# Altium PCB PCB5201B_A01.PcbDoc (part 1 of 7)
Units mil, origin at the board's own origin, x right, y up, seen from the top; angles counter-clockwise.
Board outline 4527.56 x 2362.2 mil, 6 copper layers (Top Layer, GND Layer 2, Signal Layer 3, Signal Layer 4, VCC Layer 5, Bottom Layer), stack 61.221 mil thick; 361 components, 250 nets, 1223 pads, 1068 vias.
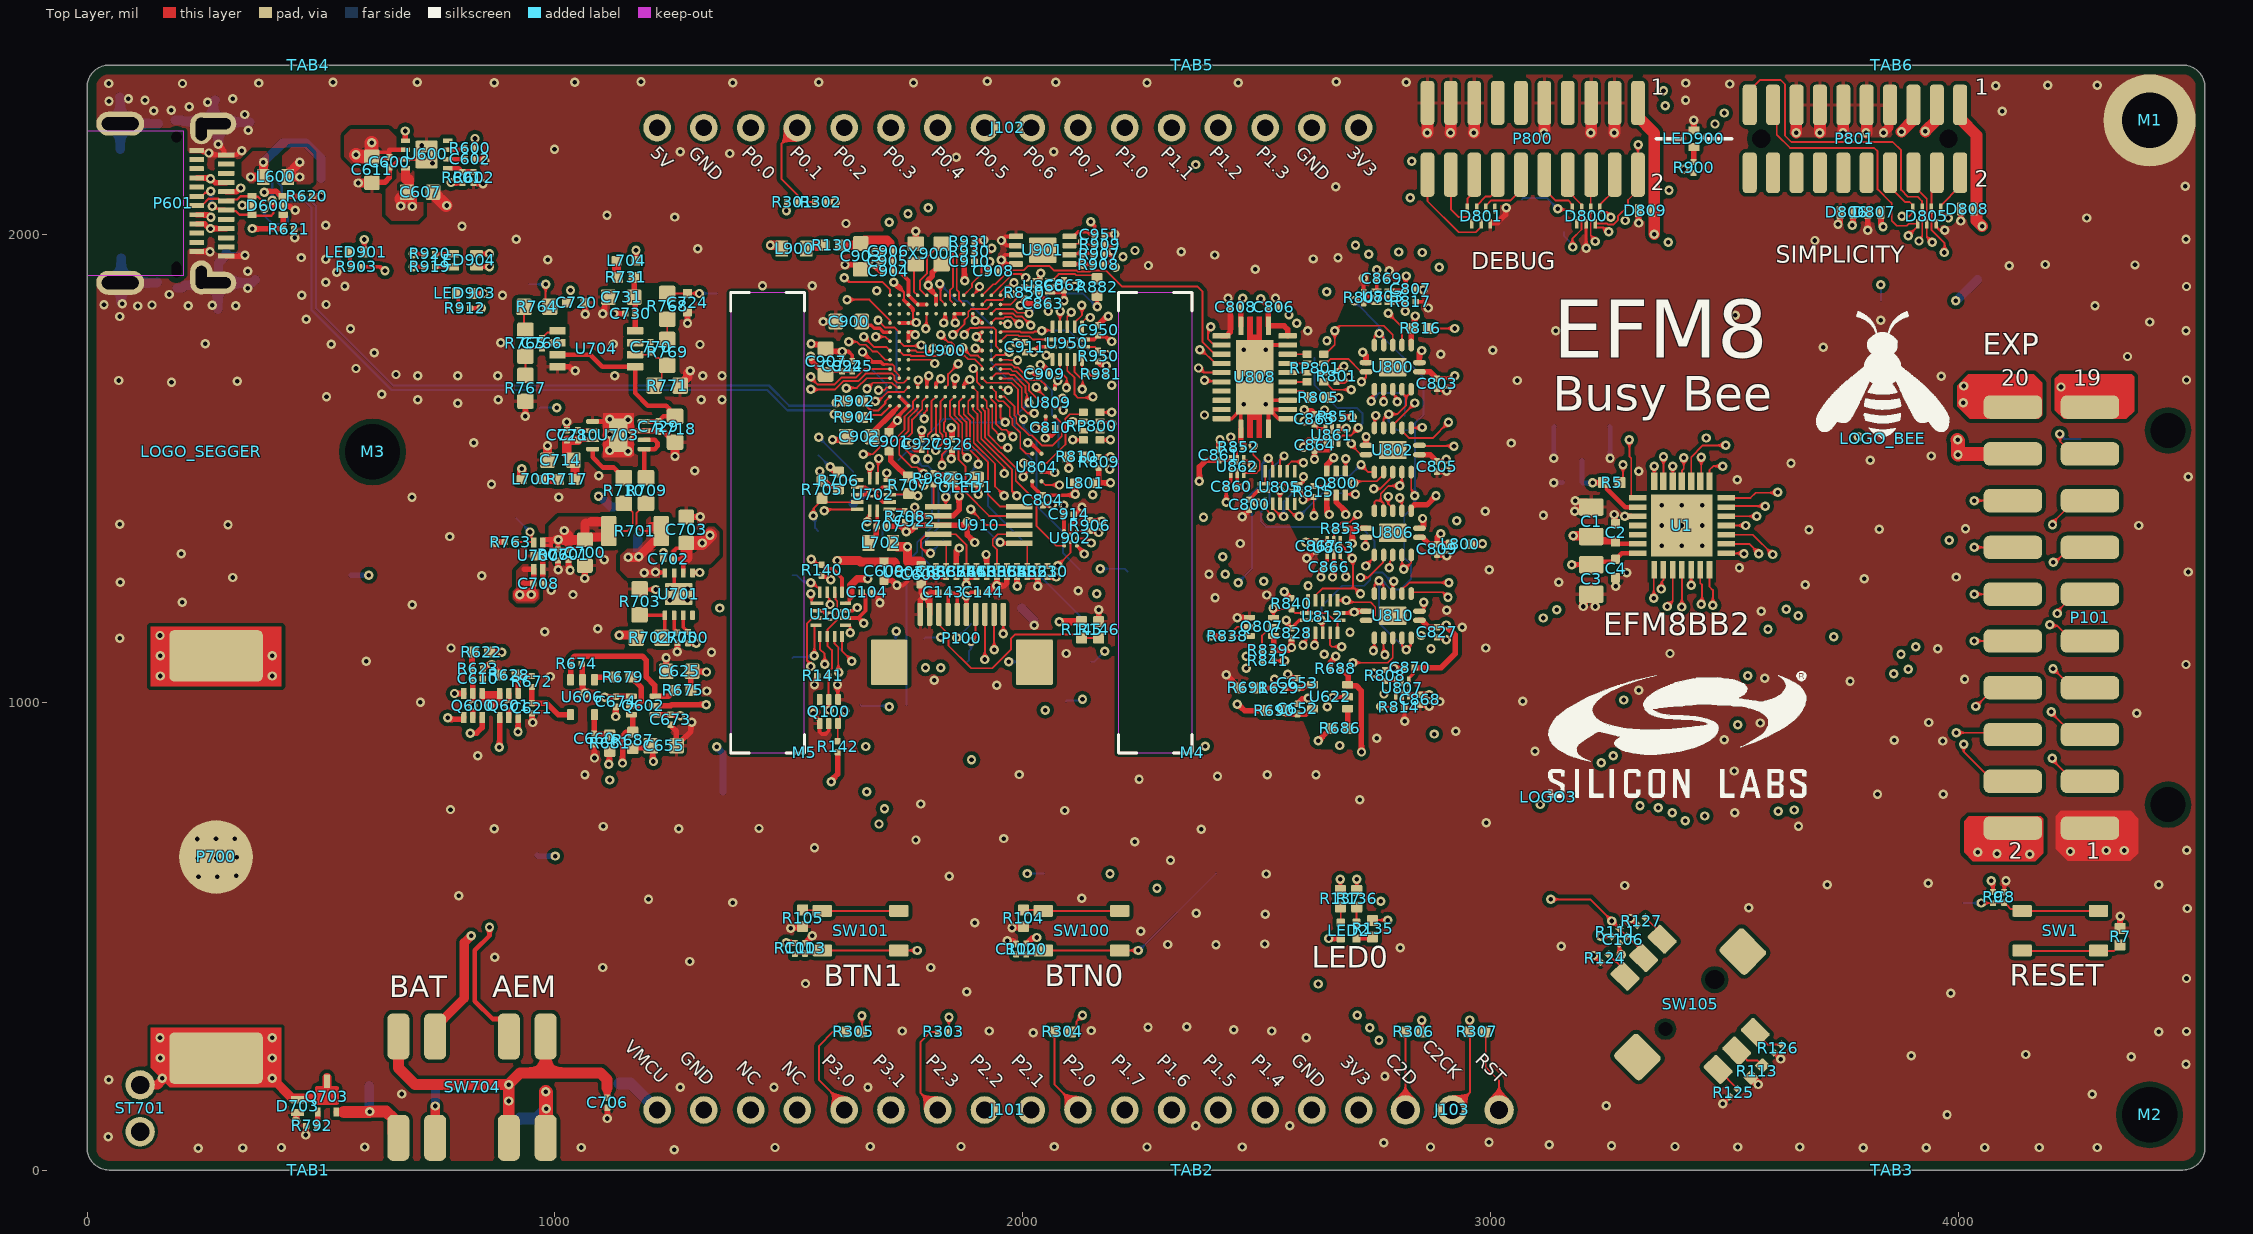
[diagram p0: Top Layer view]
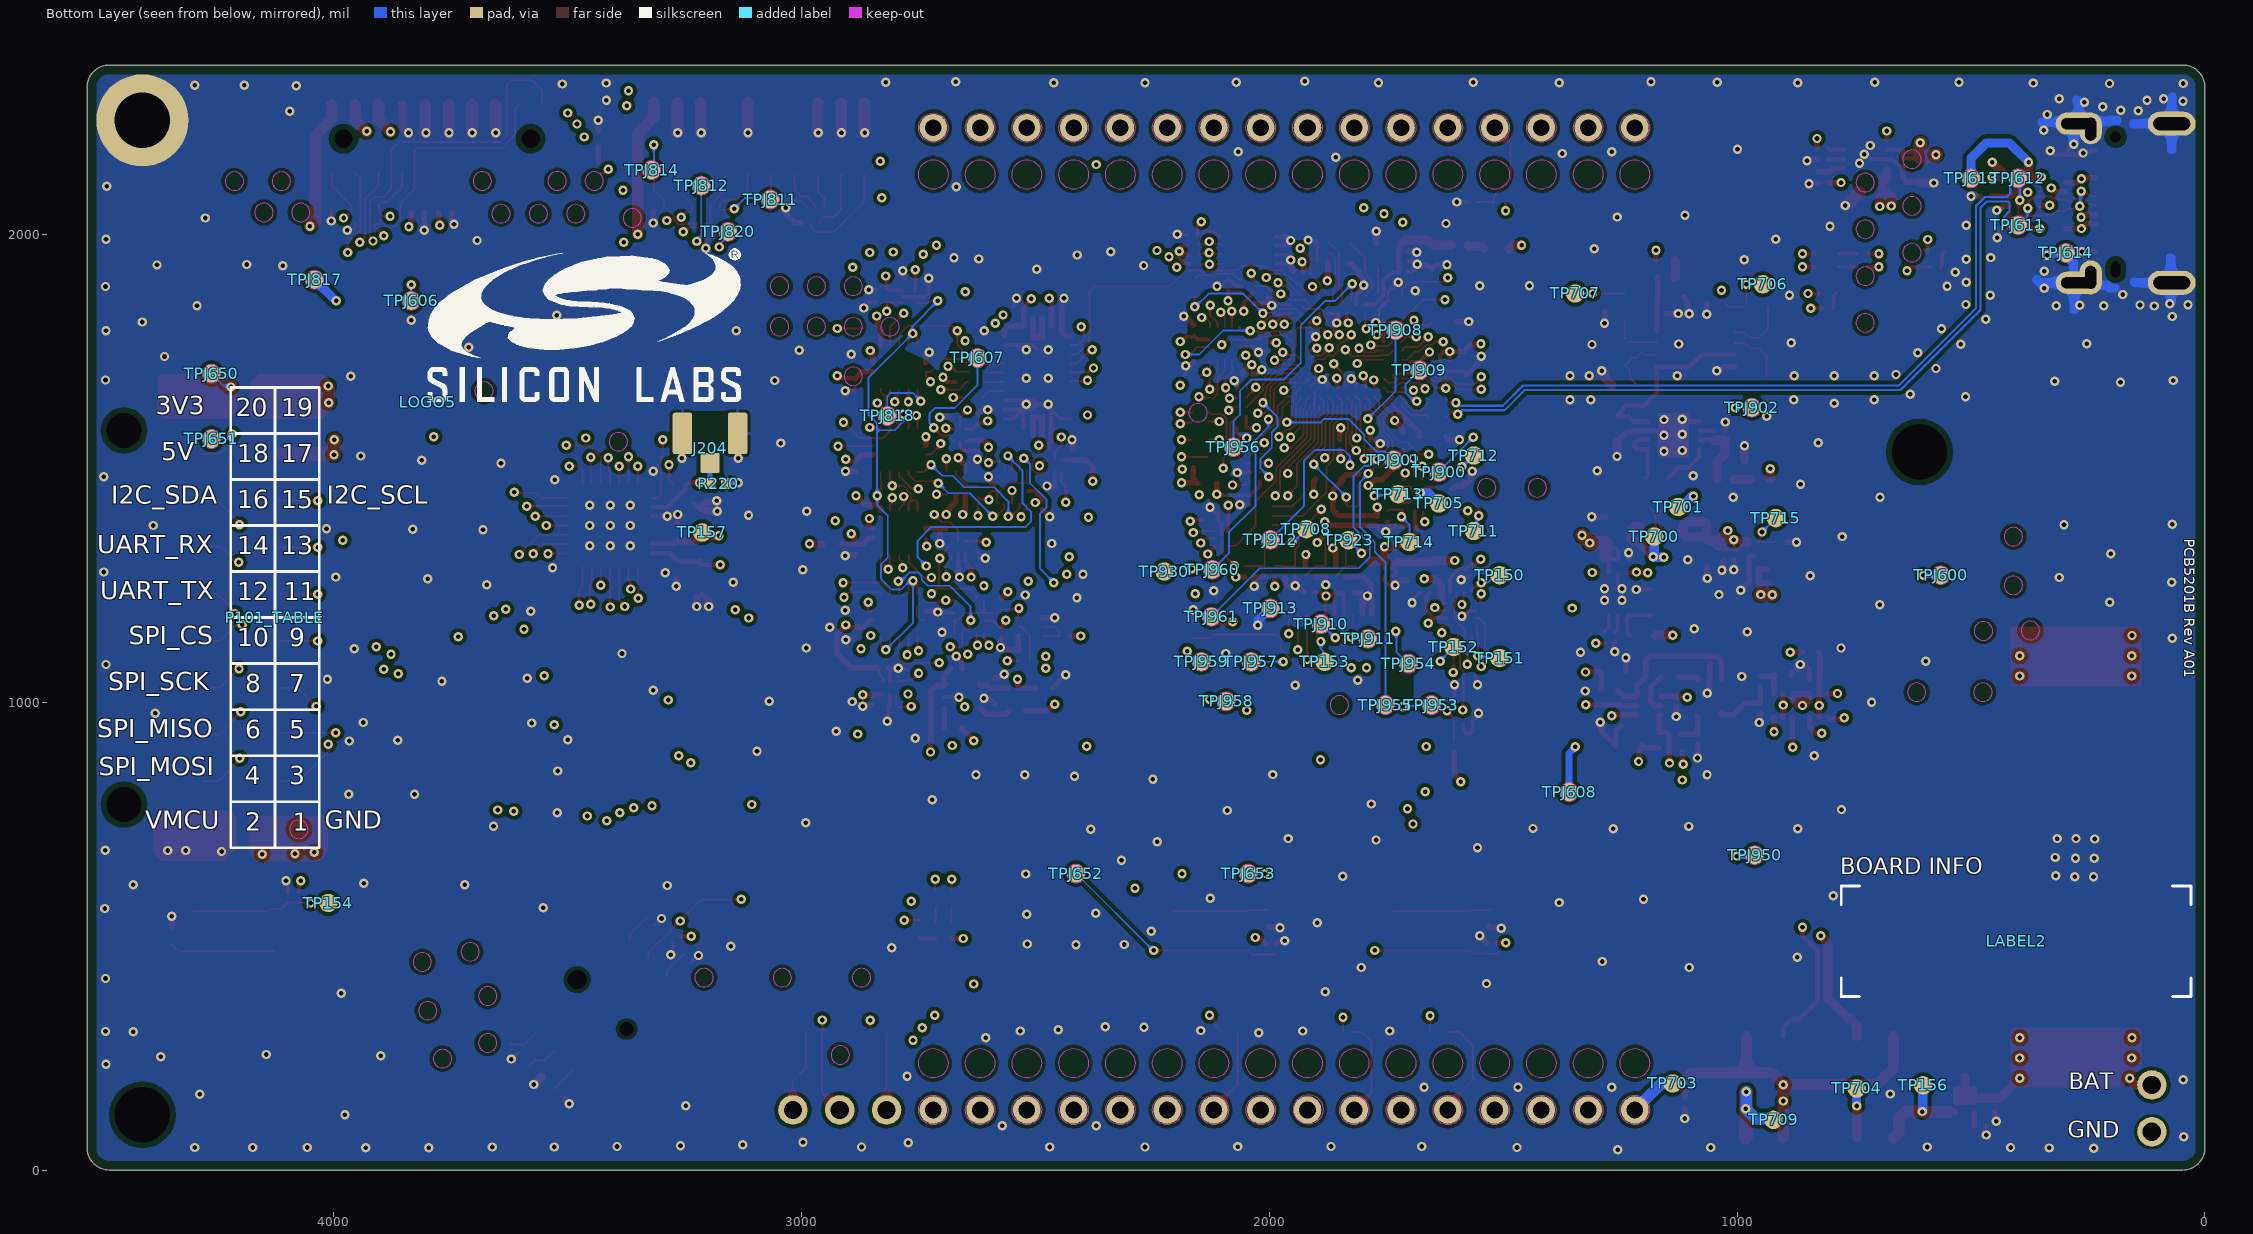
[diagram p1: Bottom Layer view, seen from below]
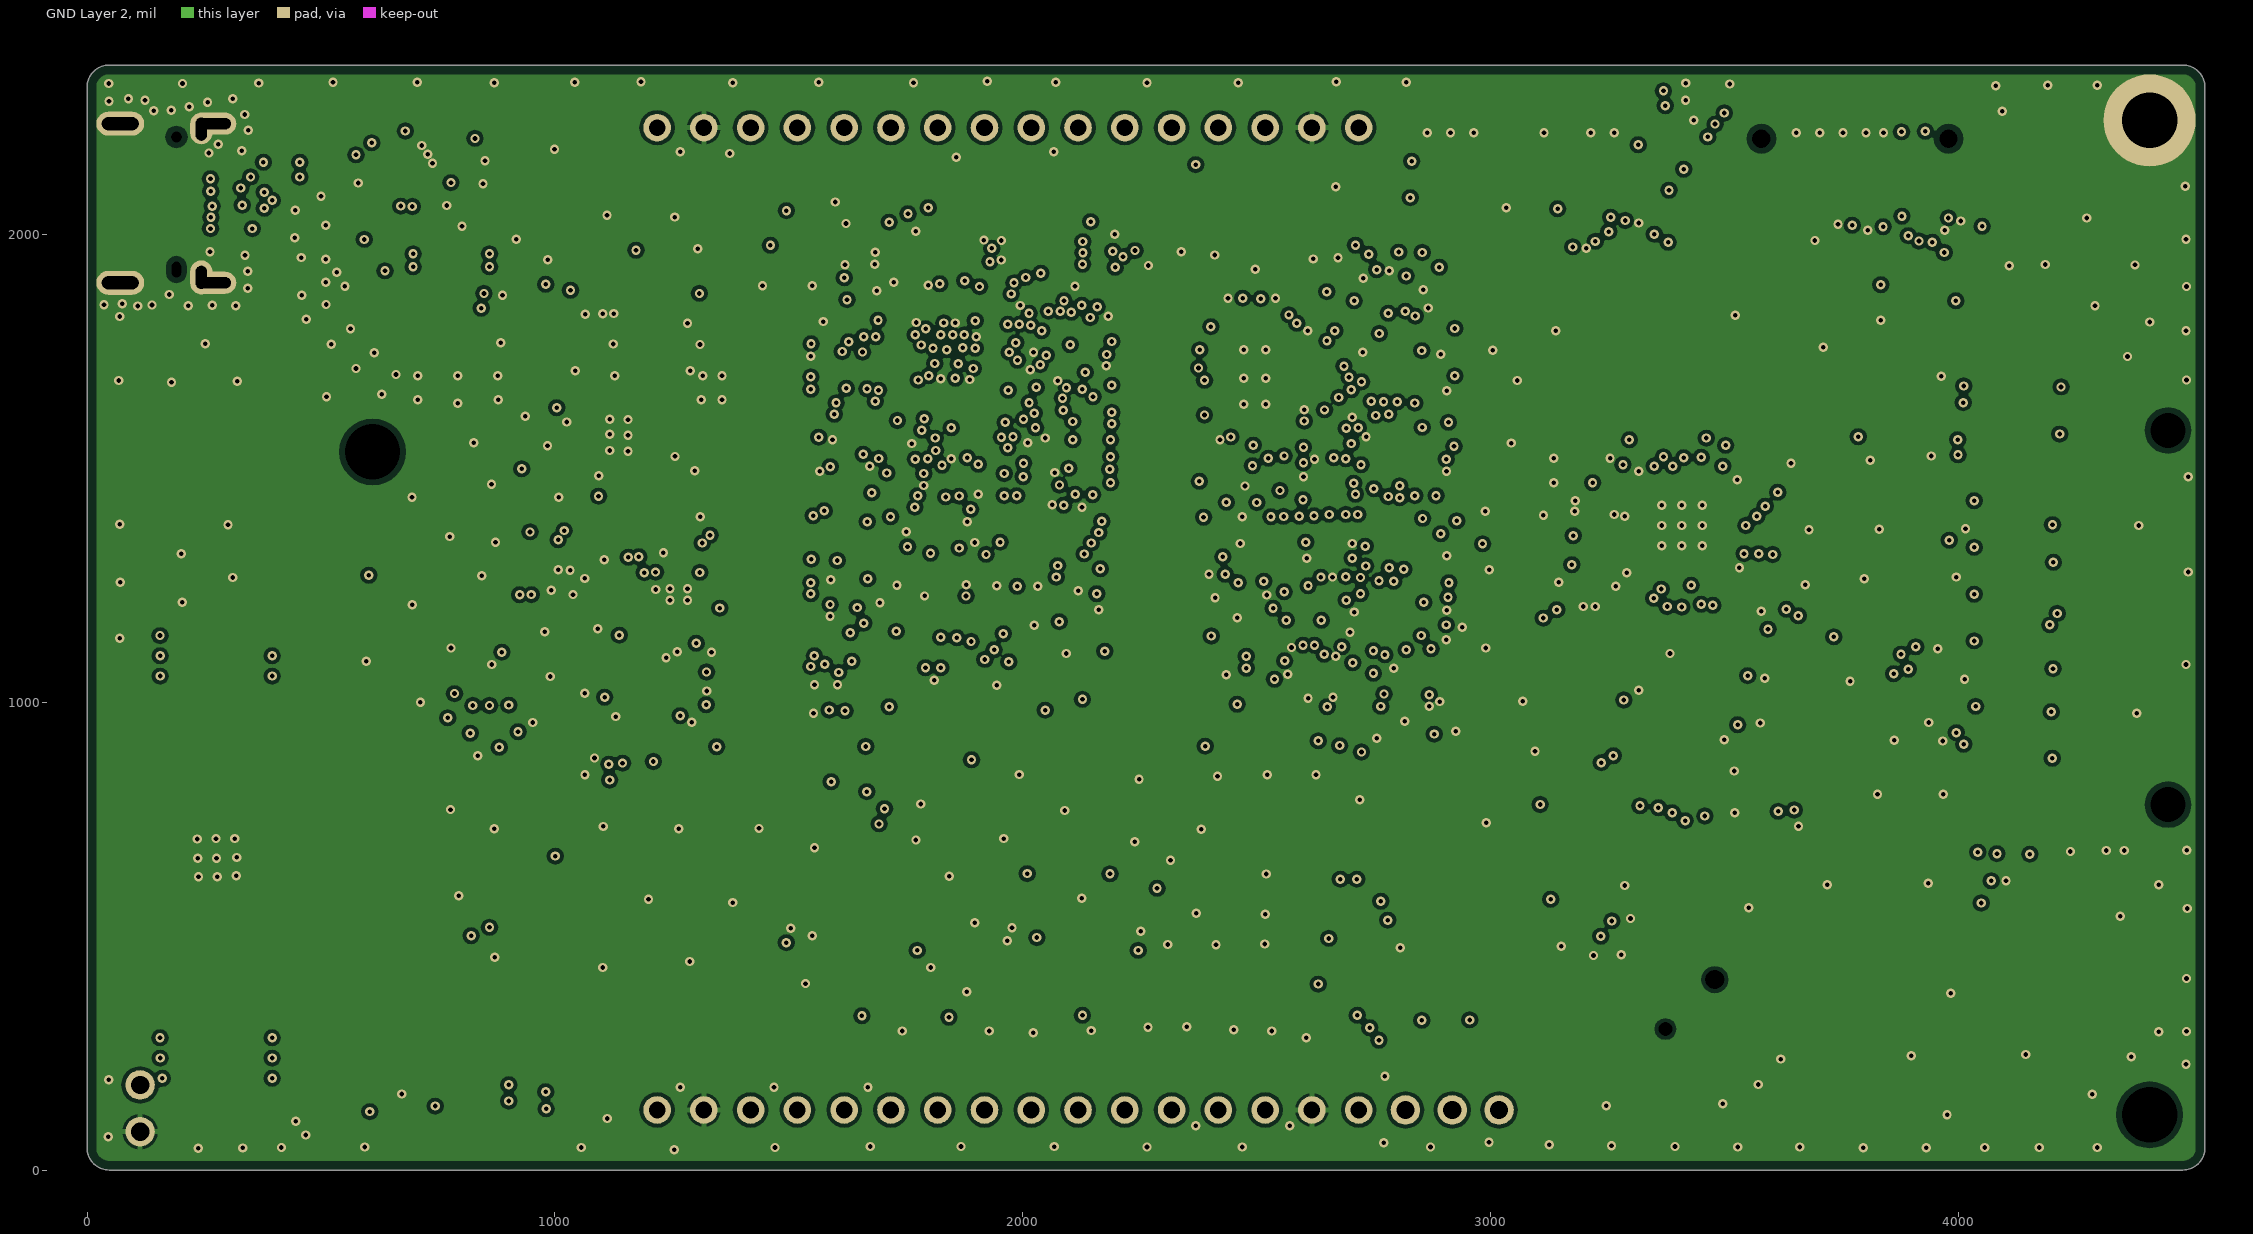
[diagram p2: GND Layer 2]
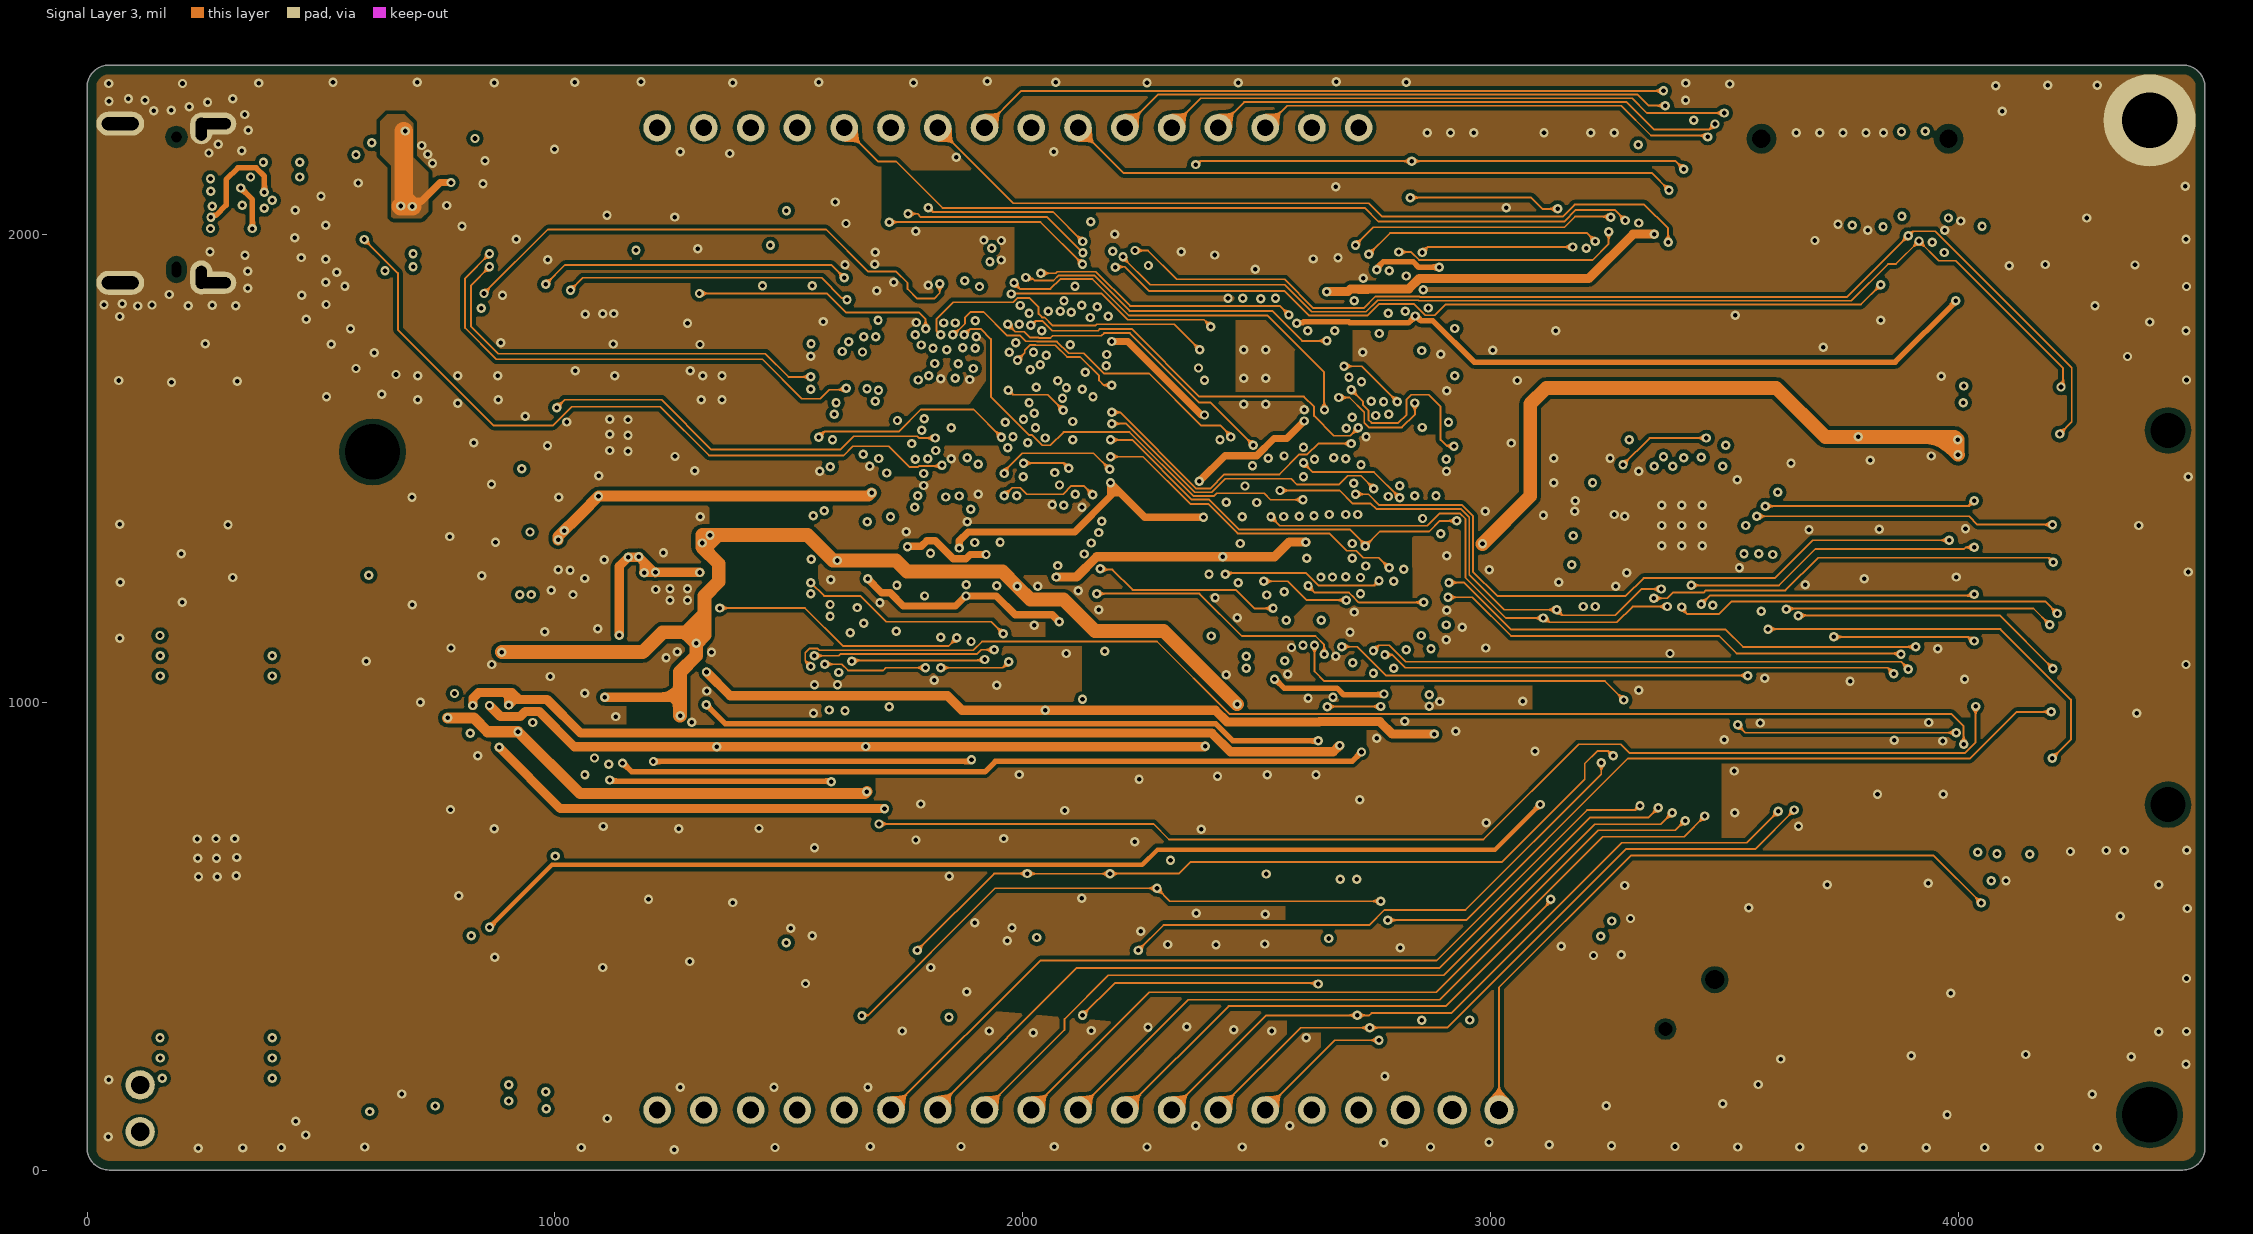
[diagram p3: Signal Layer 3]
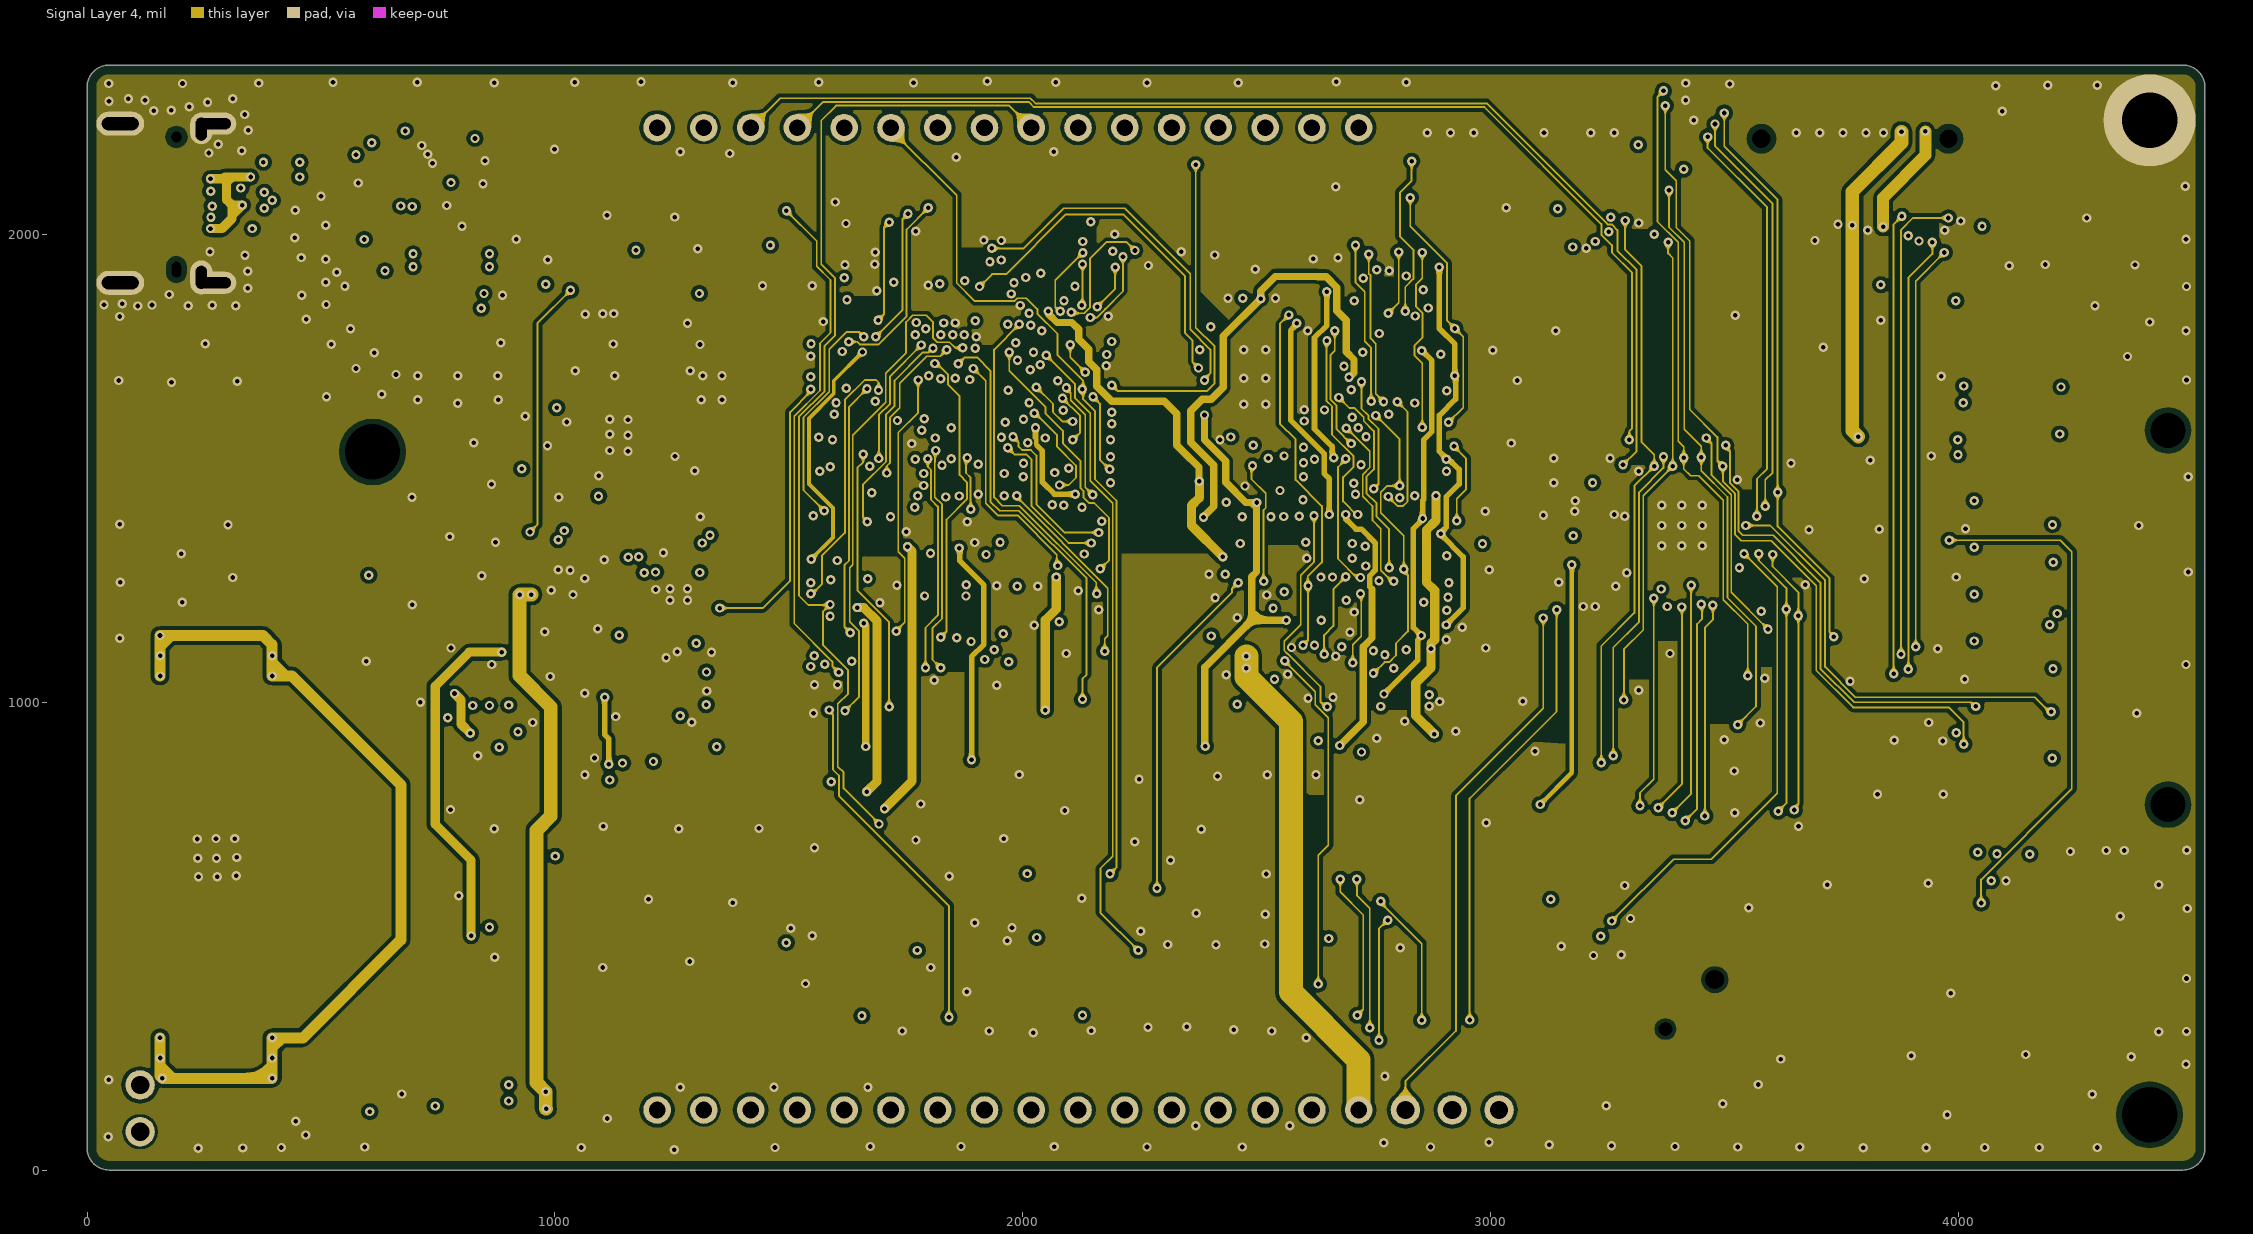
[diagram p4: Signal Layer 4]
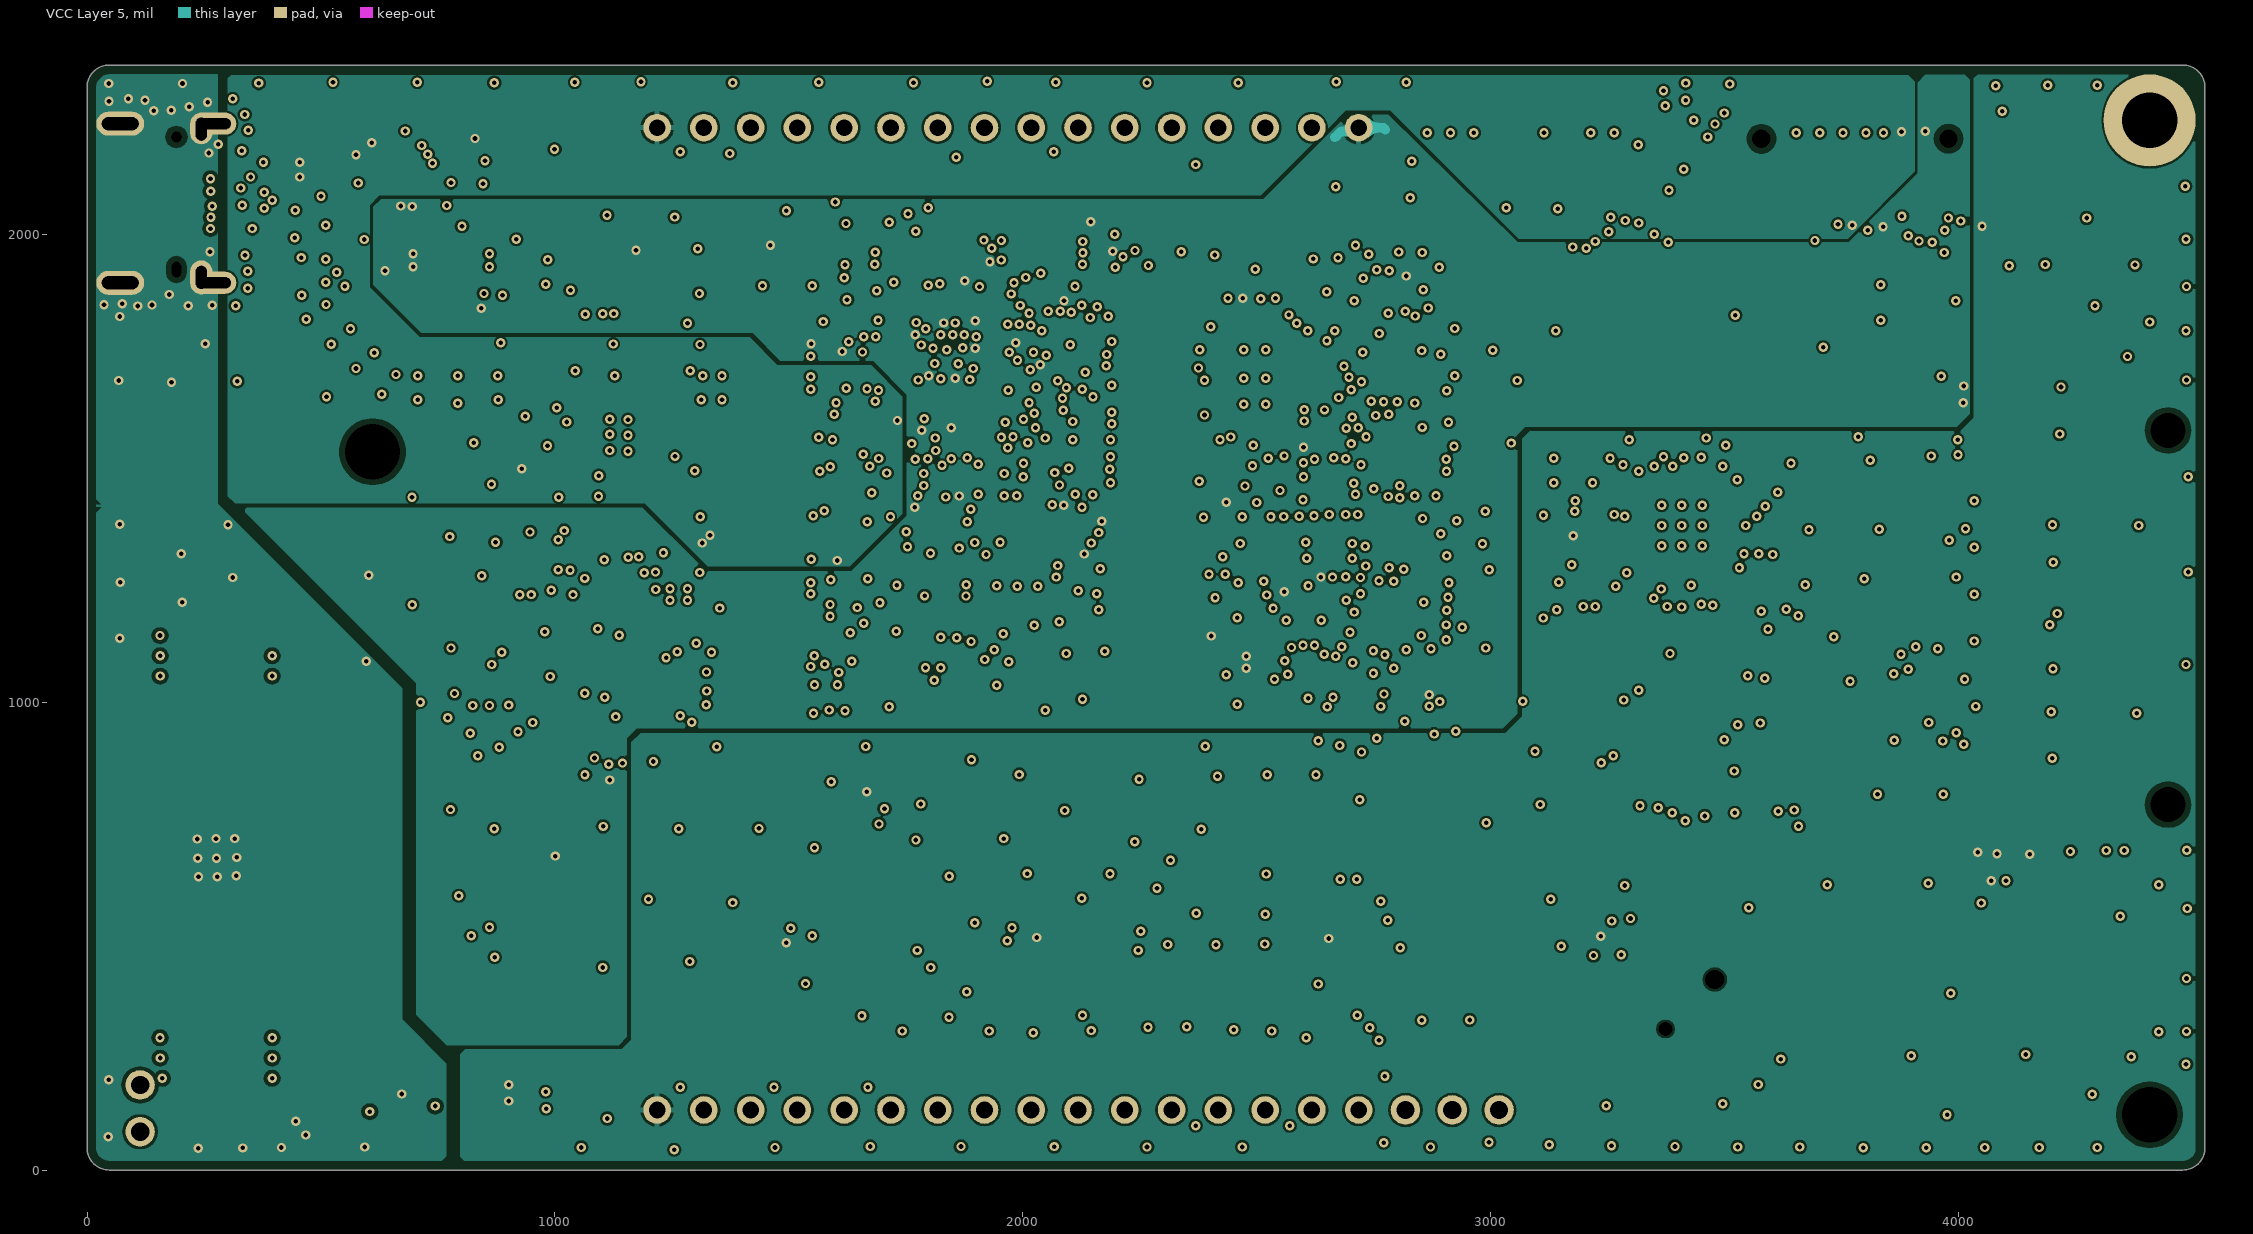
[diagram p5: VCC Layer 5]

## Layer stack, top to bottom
Top Solder: solder mask 1.1811, Solder Resist, Dk 3.5
Top Layer: signal copper 1.378
Dielectric 1: prepreg 3.937, FR-4, Dk 4.2
GND Layer 2: signal copper 1.378
Dielectric 2: core 18.1102, Core-009, Dk 4.2
Signal Layer 3: signal copper 1.378
Dielectric 3: prepreg 8.8583, PP-006, Dk 4.2
Signal Layer 4: signal copper 1.378
Dielectric 4: core 18.1102, Core-009, Dk 4.2
VCC Layer 5: signal copper 1.378
Dielectric  5: prepreg 3.937, FR-4, Dk 4.2
Bottom Layer: signal copper 1.378
Bottom Solder: solder mask 1.1811, Solder Resist, Dk 3.5

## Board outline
0,47.24 0,2314.96 cw(c47.24,2314.96) 47.24,2362.2 4480.32,2362.2 cw(c4480.32,2314.96) 4527.56,2314.96 4527.56,47.24 cw(c4480.32,47.24) 4480.32,0 47.24,0 cw(c47.24,47.24)

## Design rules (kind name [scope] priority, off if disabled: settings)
BoardOutlineClearance BoardOutlineClearance_IGNORE_USB [HasFootprint('FCI_10137065_USB-C_RCPT') and IsKeepOut] p1: gap=19.68 ignorepadtopadclearanceinfootprint=FALSE except(0: Region-OutlineEdge Region-CavityEdge Region-CutoutEdge Region-SplitBarrior Region-SplitContinuation; 10.24: Arc-CutoutEdge Track-CutoutEdge SMDPad-CutoutEdge THPad-CutoutEdge Via-CutoutEdge Fill-CutoutEdge Poly-CutoutEdge Text-CutoutEdge; 15.75: THPad-OutlineEdge)
BoardOutlineClearance [Not HasFootprint('TAB50.5_T1.6_W2.4') or not HasFootprint('FCI_10137065_USB-C_RCPT')] p2: gap=19.68 ignorepadtopadclearanceinfootprint=FALSE except(10.24: Arc-CutoutEdge Track-CutoutEdge SMDPad-CutoutEdge THPad-CutoutEdge Via-CutoutEdge Fill-CutoutEdge Poly-CutoutEdge Region-CutoutEdge Text-CutoutEdge; 15.75: THPad-OutlineEdge)
Clearance Clearance_NPL [(ObjectKind = 'Pad') And (Layer = 'MultiLayer') And (PadIsPlated = 'False')] p1: gap=11.81 ignorepadtopadclearanceinfootprint=FALSE
Clearance Clearance_Polygon_GND [InNet('GND') and InPolygon] p2: gap=7.87 ignorepadtopadclearanceinfootprint=FALSE
Clearance Clearance_Polygon_General [InPolygon] p3: gap=4.92 ignorepadtopadclearanceinfootprint=FALSE
Clearance Clearance_Via_Track [IsVia vs IsTrack] p4: gap=3.5 ignorepadtopadclearanceinfootprint=FALSE except(0: Arc-Hole Track-Hole SMDPad-Hole THPad-Hole Via-Hole Fill-Hole Poly-Hole Region-Hole Text-Hole)
Clearance [All] p5: gap=3.94 ignorepadtopadclearanceinfootprint=FALSE
ComponentClearance ComponentClearance_IGNORE [HasFootprint('TESTJIGG_PCB4002_M14') OR HasFootprint('TAB50.5_T1.6_W2.4') OR HasFootprint('TP_6.0X6.0_MILLOUT_5.0X5.0_TH') Or InComponent('M1')] p1: gap=0 collisioncheckmode=3 verticalgap=0 showdistances=FALSE
ComponentClearance [All] p2: gap=7.87 collisioncheckmode=3 verticalgap=10 showdistances=FALSE
DiffPairsRouting DiffPairsRouting_90OHM [InDifferentialPair('USB_90') or InDifferentialPair('USB_90_U900')] p1: maxlimit=10 minlimit=4.72 mostfreqgap=10 toplayer_maxgap=4.72 toplayer_prefgap=4.72 toplayer_minwidth=4.72 toplayer_maxwidth=4.72 toplayer_prefwidth=4.72 bottomlayer_maxgap=4.72 bottomlayer_prefgap=4.72 bottomlayer_minwidth=4.72 bottomlayer_maxwidth=4.72 bottomlayer_prefwidth=4.72 impedanceprofiledriven=TRUE impedanceprofileid={B4300C99-598D-4438-91CE-854F904B181D} impedanceprofilevalue=90.000000 maxuncoupledlength=1968.5
HoleSize [All] p1: absolutevalues=TRUE maxlimit=393.7 minlimit=3.94 maxpercent=80.000 minpercent=20.000
HoleToHoleClearance HoleToHoleClearance_general [Not InComponent('P601')] p1: gap=10 allowstackedmicrovias=TRUE
MinimumSolderMaskSliver MinimumSolderMaskSliver_IGNORE [InComponent('LOGO*') vs InComponent('LOGO*')] p1: minsoldermaskwidth=0
MinimumSolderMaskSliver [All] p2: minsoldermaskwidth=3.94
PolygonConnect PolygonConnect_Direct_Connect [InComponent('M1') or InComponent('J1') or InComponent('P700') or InComponent('P601')] p1: connectstyle=Direct reliefconductorwidth=13 reliefentries=4 polygonreliefangle="90 Angle" airgapwidth=6
PolygonConnect PolygonConnect_IGNORE_GND_FILL [IsThruPin vs InNet('GND') and not OnLayer('GND Layer 2')] p2: connectstyle=NoConnect reliefconductorwidth=11.81 reliefentries=4 polygonreliefangle="90 Angle" airgapwidth=5.91
PolygonConnect PolygonConnect_general [All] p3: thpad.connectstyle=Relief thpad.reliefconductorwidth=11.81 thpad.reliefentries=4 thpad.polygonreliefangle="90 Angle" thpad.airgapwidth=5.91 smdpad.connectstyle=Relief smdpad.reliefconductorwidth=7.87 smdpad.reliefentries=4 smdpad.polygonreliefangle="90 Angle" smdpad.airgapwidth=5.91 via.connectstyle=Direct via.reliefconductorwidth=13 via.reliefentries=4 via.polygonreliefangle="90 Angle" via.airgapwidth=5
RoutingVias RoutingVias_Through [InDrillLayerPair('Top Layer - Bottom Layer')] p1: holewidth=9.84 width=20 viastyle="Through Hole" minholewidth=9.84 minwidth=20 maxholewidth=39.37 maxwidth=59.06 useviatemplates=TRUE viatemplateguid#1={89E5EF08-91F7-4BC1-BF72-0CDB5ADAF91B} viatemplatename#1=v51h25m0mx0(Tol8-8)
ShortCircuit ShortCircuit_General [All] p1: allowed=FALSE
SilkToSilkClearance [All] p1: silktosilkclearance=4
SilkToSolderMaskClearance [IsPad] p1: minsilkscreentomaskgap=4 clearancetoexposedcopper=TRUE
SolderMaskExpansion [All] p1: expansion=1.97 istentingtop=FALSE
UnRoutedNet [All] p1: checkbadconnections=TRUE
Width [All] p1: maxlimit=200 minlimit=3.94 preferedwidth=3.94 minimp=50.000000 maximp=50.000000 favimp=50.000000
21 further rules are at their usual default settings.

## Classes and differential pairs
net class USB: USB_DM USB_DP
net class "New Class": USB_DM USB_DP
differential pair class USB: USB1
differential pair USB1: +USB_DP -USB_DM
differential pair usb: +USB_DP -USB_DM

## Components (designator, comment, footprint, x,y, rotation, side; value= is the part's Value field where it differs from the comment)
C1 "10U" C0805 3215.55,1385.83 r90 top
C2 "100N" C0402 3267.72,1362.2 r90 top
C3 "10U" C0805 3215.55,1262.58 r270 top
C4 "100N" C0402 3267.72,1285.9 r270 top
C8 "100N" C0201 4098.43,582.68 r90 top
C102 "1N" C0201 1986.22,472.44 r90 top
C103 "1N" C0201 1534.88,473.67 r90 top
C104 "100N" C0201 1667.24,1235.18 r0 top
C106 "1N" C0201 3283.46,492.13 r225 top
C143 "100N" C0201 1830.67,1234.81 r180 top
C144 "100N" C0201 1914.35,1234.98 r0 top
C600 "100N" C0201 646.33,2154.58 r270 top
C602 "33N" C0201 818.2,2161.32 r0 top
C607 "10U" C0603 711.9,2090.45 r0 top
C608 "1U" C0402 1783.47,1272.64 r270 top
C609 "1U" C0402 1703.74,1280.51 r270 top
C610 "1N" C0201 834.65,1050.2 r0 top
C611 "10U" C0603 608.85,2138.36 r270 top
C621 "100N" C0201 950.79,987.2 r270 top
C625 "10U" C0603 1265.68,1066.16 r180 top
C632 "10N" C0201 2009.84,1279.53 r270 top
C635 "10N" C0201 1944.88,1279.53 r270 top
C638 "10N" C0201 1814.96,1279.53 r270 top
C641 "10N" C0201 1879.92,1279.53 r270 top
C652 "100N" C0201 2587.58,985.67 r90 top
C653 "100N" C0201 2587.38,1040.94 r90 top
C655 "10U" C0603 1232.44,906.95 r0 top
C660 "100N" C0201 1084.15,921.64 r270 top
C673 "100N" C0201 1247.05,962.6 r270 top
C674 "100N" C0201 1130.42,1000.85 r270 top
C700 "10U" C0603 1064.27,1319.89 r270 top
C701 "100N" C0201 1028.89,1315.43 r270 top
C702 "100N" C0201 1242.92,1305.96 r180 top
C703 "10U" C0603 1280.92,1368.56 r90 top
C705 "33N" C0201 1261.79,1137.96 r270 top
C706 "100N" C0201 1112.21,143.7 r270 top
C707 "100N" C0201 1698.82,1375.98 r0 top
C708 "100N" C0201 964.57,1253.94 r0 top
C710 "100N" C0201 1049.21,1570.87 r90 top
C714 "10U" C0603 1011.81,1517.72 r180 top
C720 "1N" C0402 1045.28,1854.33 r0 top
C724 "1N" C0402 1283.46,1854.33 r270 top
C728 "100N" C0201 1025.59,1570.87 r90 top
C729 "2N2" C0201 1221.46,1589.57 r270 top
C730 "100N" C0201 1161.29,1831.06 r180 top
C731 "10U" C0603 1141.73,1866.14 r180 top
C766 "10P" C0201 972.44,1767.72 r90 top
C770 "10P" C0201 1204.72,1758.86 r90 top
C800 "100N" C0201 2484.25,1422.24 r270 top
C803 "100N" C0201 2885.83,1681.1 r270 top
C804 "100N" C0201 2043.31,1432.09 r270 top
C805 "100N" C0201 2885.83,1503.94 r270 top
C806 "100N" C0201 2537.4,1844.49 r0 top
C807 "100N" C0201 2828.74,1882.87 r0 top
C808 "100N" C0201 2454.72,1844.49 r180 top
C809 "100N" C0201 2885.83,1326.77 r270 top
C810 "100N" C0201 2059.06,1586.61 r0 top
C827 "100N" C0201 2885.83,1149.61 r270 top
C828 "100N" C0201 2574.8,1147.64 r270 top
C860 "100N" C0201 2445.87,1460.63 r0 top
C861 "100N" C0201 2419.29,1528.54 r90 top
C862 "100N" C0201 2088.58,1891.73 r90 top
C863 "100N" C0201 2043.31,1852.36 r180 top
C864 "100N" C0201 2624.02,1549.21 r270 top
C865 "100N" C0201 2624.02,1605.32 r90 top
C866 "100N" C0201 2654.53,1288.39 r0 top
C867 "100N" C0201 2626.97,1333.66 r270 top
C868 "100N" C0201 2849.45,1005.47 r270 top
C869 "100N" C0201 2767.48,1905.63 r0 top
C870 "100N" C0201 2827.32,1074.17 r180 top
C900 "1U" C0603 1627.95,1813.98 r180 top
C901 "1U" C0402 1714.57,1557.09 r270 top
C902 "4U7" C0603 1650.59,1567.91 r180 top
C903 "10U" C0603 1653.79,1953.35 r270 top
C904 "10N" C0201 1712.5,1921.35 r180 top
C905 "10N" C0201 1712.02,1942.98 r180 top
C906 "10N" C0201 1712.5,1964.42 r180 top
C907 "4U7" C0603 1578.74,1728.35 r270 top
C908 "100N" C0201 1937.01,1921.26 r0 top
C909 "100N" C0201 2046.44,1701.75 r180 top
C910 "100N" C0201 1886.18,1942.24 r0 top
C911 "100N" C0201 2004.92,1758.86 r270 top
C914 "100N" C0201 2098.43,1401.57 r0 top
C921 "4U7" C0603 1874.02,1476.38 r0 top
C922 "100N" C0201 1769.69,1386.81 r270 top
C924 "100N" C0201 1614.17,1718.5 r270 top
C925 "100N" C0201 1635.83,1718.5 r270 top
C926 "100N" C0201 1849.41,1551.18 r270 top
C927 "100N" C0201 1784.45,1551.18 r270 top
C950 "10N" C0201 2161.42,1795.28 r90 top
C951 "100N" C0201 2165.25,1999.15 r0 top
D600 "DT1446-04" SOT563_DIODES 385.7,2061.96 r180 top
D703 "ESD" X2-DFN1006-2 449.8,136.81 r270 top
D800 "PUSB3AB6" DFN2111-7_M050_1.2X2.1_NXP 3204.72,2039.37 r270 top
D801 "PUSB3AB6" DFN2111-7_M050_1.2X2.1_NXP 2980.32,2039.37 r270 top
D805 "PUSB3AB6" DFN2111-7_M050_1.2X2.1_NXP 3933.07,2039.37 r270 top
D806 "ESD" X2-DFN1006-2 3761.81,2047.24 r180 top
D807 "ESD" X2-DFN1006-2 3820.87,2047.24 r180 top
D808 "ESD" X2-DFN1006-2 4019.62,2054.37 r180 top
D809 "ESD" X2-DFN1006-2 3330.71,2051.18 r180 top
J101 "1X16 2.54MM" HDR_M254-1X16_NO_3D 1218.5,128.43 r0 top locked
J102 "1X16 2.54MM" HDR_M254-1X16_NO_3D 1218.5,2228.43 r0 top locked
J103 "1X3 2.54MM" HDR_M254-1X3_NO_3D 2818.5,128.43 r0 top
J204 "U.FL" HRS_U.FL-R-SMT 3195.87,1574.8 r180 bottom
L600 "742792662" COIL_WURTH_CBF_0603 402.96,2123.09 r0 top
L700 "742792796" COIL_0402 949.8,1476.38 r0 top
L702 "74279266" COIL_WURTH_CBF_0603 1696.85,1340.55 r180 top
L704 "742792796" COIL_0402 1152.83,1943.9 r180 top
L800 "742792796" COIL_0402 2936,1337.73 r180 top
L801 "742792796" COIL_0402 2132.87,1468.5 r180 top
L900 "74279266" COIL_WURTH_CBF_0603 1511.43,1969.86 r0 top
LABEL2 "Comment" LABEL_4CORNERS_19.0X6.0 403.54,489.17 r180 bottom
LED2 "RGB" LED_LUMEX_SML-LX0404-4 2696.85,511.81 r0 top
LED900 "YELLOW" LED_0402_CAT2 3435.04,2204.72 r90 top
LED901 "BLUE" LED_0402_CAT2 575.79,1962.6 r0 top
LED903 "RED" LED_0402 807.09,1874.02 r180 top
LED904 "LED_G_R" LED_AVAGO_HSMF-C165-4 807.09,1944.88 r0 top
LOGO3 "Comment" LOGO_SILABS_W14.0_SILK 3124.02,797.24 r0 top
LOGO5 "Comment" LOGO_SILABS_W18.0 3799.21,1641.73 r180 bottom
LOGO_BEE "Comment" LOGO_BEE_H7.0 3838.58,1562.99 r0 top
LOGO_SEGGER "Comment" LOGO_SEGGER_10.0X5.0_SM 244.1,1535.43 r0 top
M1 "HOLE_PTH_3MM" HOLE_3.0_5.0_PL 4409.45,2244.09 r0 top
M2 "Comment" HOLE_3.0_NPL 4409.45,118.11 r0 top
M3 "Comment" HOLE_3.0_NPL 610.24,1535.43 r90 top
M4 "Comment" ADHESIVE_PAD_25.0X4.0 2362.21,891.73 r90 top
M5 "Comment" ADHESIVE_PAD_25.0X4.0 1533.47,891.73 r90 top
OLED1 "Comment" OLED_LS013B7DH03 1878.94,1459.65 r0 top
P100 "L-KLS1-242D-1.2-10" KLS_KLS1-242D_FPC_0.5-10 1781.5,1187.99 r0 top
P101 "HEADER_2X10_2.54MM_TH" WCON_1125B-1210_HOR_PEG-2X10 4448.82,781.1 r90 top
P101_TABLE "Comment" LABEL_P101_PIN_TABLE_SL 4125.98,1181.1 r180 bottom
P601 "FCI_10137065_USB-C_RCPT" FCI_10137065_USB-C_RCPT 190.94,2066.93 r270 top
P700 "CR2032" BAT_HOLD_MPD_BK-912_CR2032 275.59,669.29 r270 top
P800 "HEADER_DEBUG_ETM" WCON_3132_HDR_M127_SMD-2X10 3090.55,2204.72 r180 top
P801 "HEADER_2X10_1.27MM_SMD" HDR_SULLINS_M127_PEG-2X10 3979.53,2204.72 r180 top
Q100 "DMN5L06VK" SOT563 1585.62,979.91 r270 top
Q600 "BSS84" SOT563 824.8,993.11 r90 top
Q601 "DMN5L06VK" SOT563 901.58,993.11 r90 top
Q602 "BSS84" SOT563 1188.98,993.11 r0 top
Q703 "DMG3415" X2-DFN2015-3_DIODES 512.8,159.45 r90 top
Q800 "DMN5L06VK" SOT563 2670.28,1468.5 r270 top
Q807 "DMN5L06VK" SOT563 2510.83,1161.42 r180 top
R5 "0R" R0402 3259.84,1469.49 r0 top
R7 "100R" R0402 4346.46,499.02 r270 top
R9 "1K" R0201 4074.8,582.68 r270 top
R100 "1M" R0201 2007.87,472.44 r90 top
R101 "1M" R0201 1512.96,473.75 r90 top
R104 "100R" R0402 2001.84,538.18 r270 top
R105 "100R" R0402 1529.53,538.39 r270 top
R111 "10K" R0201 3267.72,507.87 r225 top
R113 "100R" R0402 3569.29,210.82 r45 top
R124 "15K" R0201 3244.09,452.76 r45 top
R125 "10K" R0201 3519.68,165.35 r45 top
R126 "33K" R0201 3614.17,259.84 r45 top
R127 "60K4" R0201 3322.83,531.5 r45 top
R130 "1R" R0402 1592.69,1977.14 r0 top
R135 "698R" R0402 2748.03,515.75 r90 top
R136 "910R" R0402 2714.31,580.1 r90 top
R137 "2K32" R0402 2679.2,580.22 r90 top
R140 "100K" R0201 1570.4,1282.5 r90 top
R141 "10M" R0201 1572.53,1056.38 r0 top
R142 "100K" R0201 1604.57,904.83 r270 top
R145 "0R" R0402 2126.26,1154.82 r90 top
R146 "0R" R0402 2162.68,1154.8 r270 top
R220 "49R9" R0402 3178.15,1467.52 r0 bottom
R301 "0R" R0201 1507.87,2069.44 r0 top
R302 "0R" R0201 1568.73,2069.45 r180 top
R303 "0R" R0201 1830.71,295.28 r180 top
R304 "0R" R0402 2084.65,295.28 r180 top
R305 "1K" R0402 1637.8,295.28 r180 top
R306 "1K" R0402 2834.65,295.28 r180 top
R307 "1K" R0402 2971.27,295.28 r180 top
R600 "10K" R0201 818.2,2184.94 r0 top
R601 "180K" R0201 802.45,2121.95 r270 top
R602 "110K" R0201 826.07,2121.95 r90 top
R620 "5K1" R0201 469.44,2081.91 r180 top
R621 "5K1" R0201 431.1,2011.81 r180 top
R622 "47R" R0402 842.52,1107.28 r0 top
R623 "10K" R0201 834.65,1071.85 r180 top
R628 "1M" R0402 901.58,1058.07 r180 top
R629 "1K" R0201 2547.98,1030.04 r180 top
R630 "4K7" R0201 2053.15,1279.53 r270 top
R631 "10K" R0201 2031.5,1279.53 r90 top
R633 "47K" R0201 1988.19,1279.53 r270 top
R634 "47K" R0201 1966.54,1279.53 r90 top
R636 "47K" R0201 1858.27,1279.53 r90 top
R637 "47K" R0201 1836.61,1279.53 r90 top
R639 "47K" R0201 1923.23,1279.53 r90 top
R640 "47K" R0201 1901.58,1279.53 r90 top
R672 "1K" R0201 950.79,1044.29 r90 top
R674 "4K7" R0201 1045.68,1082.27 r0 top
R675 "3R3" R0402 1272.93,1025.59 r0 top
R679 "0R" R0402 1145.08,1053.59 r0 top
R681 "33R" R0402 1117.32,912.27 r270 top
R686 "0R" R0402 2677.49,944.27 r180 top
R687 "3R3" R0402 1166.51,918.61 r270 top
R688 "4K7" R0201 2668.75,1072.15 r180 top
R690 "33R" R0402 2538.24,982.05 r180 top
R691 "1M" R0402 2481.39,1030.97 r180 top
R700 "10K" R0201 1284.51,1138.24 r270 top
R701 "4R7" R1206 1171.26,1366.14 r180 top
R702 "180K" R0603 1201.4,1137.8 r180 top
R703 "110K" R0603 1181.1,1214.79 r270 top
R705 "267R" R0402 1570.87,1453.92 r270 top
R706 "10K2" R0402 1606.3,1474.16 r90 top
R707 "24K9" R0402 1755.91,1464.15 r270 top
R708 "1M" R0201 1748.03,1396.65 r90 top
R709 "1K8" R0603 1194.88,1452.76 r270 top
R710 "1K8" R0603 1147.64,1452.76 r270 top
R717 "10R" R0402 1025.59,1476.38 r0 top
R718 "12K" R0603 1256.89,1583.66 r90 top
R731 "1R" R0402 1151.57,1908.46 r180 top
R760 "330K" R0201 1006.81,1315.09 r90 top
R763 "100K" R0201 904.69,1342.43 r0 top
R764 "90R9" R0603 961.61,1845.47 r0 top
R765 "51K" R0603 937.01,1767.72 r90 top
R767 "160R" R0603 937.01,1671.26 r90 top
R768 "90R9" R0603 1240.16,1846.46 r90 top
R769 "51K" R0603 1240.16,1748.03 r90 top
R771 "51K" R0603 1240.16,1677.17 r180 top
R792 "1K" R0201 480.32,94.49 r0 top
R801 "47K" R0201 2671.23,1696.57 r270 top
R805 "33R" R0402 2631.89,1651.57 r0 top
R807 "100K" R0201 2729.33,1865.16 r90 top
R808 "100K" R0201 2774.61,1057.09 r90 top
R809 "100K" R0201 2162.4,1512.8 r270 top
R810 "33R" R0402 2114.17,1524.61 r0 top
R814 "100K" R0201 2804.41,989.37 r180 top
R815 "1K" R0201 2621.66,1450.48 r270 top
R816 "100K" R0402 2850.39,1799.21 r180 top
R817 "100K" R0201 2828.74,1856.3 r180 top
R838 "100K" R0201 2437.05,1141.59 r180 top
R839 "10M" R0201 2523.62,1111.22 r180 top
R840 "100K" R0201 2574.8,1210.63 r90 top
R841 "1K" R0201 2523.79,1088.65 r0 top
R850 "100K" R0201 2003.93,1875.68 r90 top
R851 "100K" R0201 2673.22,1610.72 r180 top
R852 "100K" R0201 2460.63,1545.28 r180 top
R853 "100K" R0201 2680.12,1371.06 r180 top
R882 "220R" R0402 2159.45,1887.8 r270 top
R900 "2K05" R0201 3434.43,2143.32 r90 top
R902 "33R" R0402 1639.76,1643.7 r0 top
R903 "5K76" R0201 575.79,1931.1 r180 top
R904 "33R" R0402 1639.76,1609.25 r0 top
R906 "10K" R0201 2143.7,1377.95 r90 top
R907 "4K7" R0201 2163.96,1957.7 r180 top
R908 "4K7" R0201 2161.36,1935.75 r180 top
R909 "10K" R0201 2164.4,1978.37 r180 top
R912 "2K15" R0201 807.09,1842.52 r180 top
R919 "1K" R0201 732.28,1931.1 r0 top
R920 "2K37" R0201 732.28,1958.66 r0 top
R930 "1K" R0201 1885.91,1963.13 r0 top
R931 "1K" R0201 1885.83,1984.25 r0 top
R950 "100K" R0201 2161.42,1740.16 r270 top
R981 "100K" R0201 2167.32,1701.77 r0 top
R982 "10K" R0201 1809.2,1477.61 r270 top
RP800 "33R" RES_MNR04-8 2147.64,1590.55 r90 top
RP801 "33R" RES_MNR04-8 2625.98,1714.57 r90 top
ST701 "2X1 2.54MM" HDR_M254-1X2 113.19,81.89 r90 top
SW1 "PTS810" SW_CK_PTS810_SJM_250 4218.5,511.81 r0 top
SW100 "PTS810" SW_CK_PTS810_SJM_250 2125.98,511.81 r0 top
SW101 "PTS810" SW_CK_PTS810_SJM_250 1653.54,511.81 r0 top
SW105 "ALPS_SKRH_4" SW_ALPS_SKRHAAE010 3427.17,354.33 r135 top
SW704 "SW_DP3T_0" CK_DP3T_JS203011SCQN 822.84,177.17 r180 top
TAB1 "Comment" TAB_V-CUT_L7.0_W2.4 472.44,0 r180 top
TAB2 "Comment" TAB_V-CUT_L7.0_W2.4 2362.2,0 r180 top
TAB3 "Comment" TAB_V-CUT_L7.0_W2.4 3858.27,0 r180 top
TAB4 "Comment" TAB_V-CUT_L7.0_W2.4 472.44,2362.2 r0 top
TAB5 "Comment" TAB_V-CUT_L7.0_W2.4 2362.2,2362.2 r0 top
TAB6 "Comment" TAB_V-CUT_L7.0_W2.4 3858.27,2362.2 r0 top
TP150 "TP_SMD" TP_1.0_SMD 1507.87,1271.65 r270 bottom
TP151 "TP_SMD" TP_1.0_SMD 1507.87,1094.49 r0 bottom
TP152 "TP_SMD" TP_1.0_SMD 1606.3,1118.11 r270 bottom
TP153 "TP_SMD" TP_1.0_SMD 1881.89,1086.61 r270 bottom
TP154 "TP_SMD" TP_1.0_SMD 4011.81,570.87 r270 bottom
TP156 "TP_SMD" TP_1.0_SMD 602.36,181.1 r180 bottom
TP157 "TP_SMD" TP_1.0_SMD 3212.6,1363.19 r270 bottom
TP700 "TP_SMD" TP_1.0_SMD 1177.17,1354.33 r90 bottom
TP701 "TP_SMD" TP_1.0_SMD 1125.98,1417.32 r90 bottom
TP703 "TP_SMD" TP_1.0_SMD 1137.8,185.04 r180 bottom
TP704 "TP_SMD" TP_1.0_SMD 744.5,174.4 r90 bottom
TP705 "TP_SMD" TP_1.0_SMD 1637.8,1425.2 r180 bottom
TP706 "TP_SMD" TP_1.0_SMD 944.88,1893.7 r90 bottom
TP707 "TP_SMD" TP_1.0_SMD 1346.46,1874.02 r90 bottom
TP708 "TP_SMD" TP_1.0_SMD 1921.26,1370.08 r90 bottom
TP709 "TP_SMD" TP_1.0_SMD 922.24,107.28 r90 bottom
TP711 "TP_SMD" TP_1.0_SMD 1562.99,1366.14 r90 bottom
TP712 "TP_SMD" TP_1.0_SMD 1562.99,1527.56 r90 bottom
TP713 "TP_SMD" TP_1.0_SMD 1724.41,1444.88 r90 bottom
TP714 "TP_SMD" TP_1.0_SMD 1700.79,1342.52 r90 bottom
TP715 "TP_SMD" TP_1.0_SMD 917.32,1393.7 r180 bottom
TP923 "TP_SMD" TP_1.0_SMD 1830.71,1346.46 r90 bottom
TP930 "TP_SMD" TP_1.0_SMD 2224.41,1279.53 r180 bottom
TPJ600 "TP_SMD" TP_1.0_SMD 565.09,1271.73 r90 bottom
TPJ606 "TP_SMD" TP_1.0_SMD 3834.79,1858.33 r90 bottom
TPJ607 "TP_SMD" TP_1.0_SMD 2624.15,1736.24 r90 bottom
TPJ608 "TP_SMD" TP_1.0_SMD 1359.39,808.13 r90 bottom
TPJ611 "TP_SMD" TP_1.0_SMD 399.61,2019.69 r180 bottom
TPJ612 "TP_SMD" TP_1.0_SMD 399.61,2120.08 r180 bottom
TPJ613 "TP_SMD" TP_1.0_SMD 500,2120.08 r180 bottom
TPJ614 "TP_SMD" TP_1.0_SMD 297.24,1960.63 r180 bottom
TPJ650 "TP_SMD" TP_1.0_SMD 4261.81,1702.68 r90 bottom
TPJ651 "TP_SMD" TP_1.0_SMD 4261.81,1562.98 r90 bottom
TPJ652 "TP_SMD" TP_1.0_SMD 2413.49,633.93 r90 bottom
TPJ653 "TP_SMD" TP_1.0_SMD 2045.39,633.93 r90 bottom
TPJ811 "TP_SMD" TP_1.0_SMD 3066.93,2074.8 r180 bottom
TPJ812 "TP_SMD" TP_1.0_SMD 3214.57,2104.33 r180 bottom
TPJ814 "TP_SMD" TP_1.0_SMD 3320.87,2137.8 r180 bottom
TPJ817 "TP_SMD" TP_1.0_SMD 4041.34,1903.54 r180 bottom
TPJ818 "TP_SMD" TP_1.0_SMD 2816.93,1612.2 r180 bottom
TPJ820 "TP_SMD" TP_1.0_SMD 3157.48,2005.91 r180 bottom
TPJ900 "TP_SMD" TP_1.0_SMD 1637.89,1492.13 r90 bottom
TPJ901 "TP_SMD" TP_1.0_SMD 1734.39,1517.73 r90 bottom
TPJ902 "TP_SMD" TP_1.0_SMD 968.5,1629.92 r180 bottom
TPJ908 "TP_SMD" TP_1.0_SMD 1730.39,1795.33 r90 bottom
TPJ909 "TP_SMD" TP_1.0_SMD 1679.19,1709.73 r90 bottom
TPJ910 "TP_SMD" TP_1.0_SMD 1889.89,1167.33 r90 bottom
TPJ911 "TP_SMD" TP_1.0_SMD 1789.49,1135.83 r90 bottom
TPJ912 "TP_SMD" TP_1.0_SMD 1998.09,1347.43 r90 bottom
TPJ913 "TP_SMD" TP_1.0_SMD 1998.09,1200.83 r90 bottom
TPJ950 "TP_SMD" TP_1.0_SMD 962.69,673.23 r90 bottom
TPJ953 "TP_SMD" TP_1.0_SMD 1653.59,994.13 r90 bottom
TPJ954 "TP_SMD" TP_1.0_SMD 1702.89,1082.73 r90 bottom
TPJ955 "TP_SMD" TP_1.0_SMD 1752.09,994.13 r90 bottom
TPJ956 "TP_SMD" TP_1.0_SMD 2076.89,1545.33 r90 bottom
TPJ957 "TP_SMD" TP_1.0_SMD 2039.31,1086.58 r180 bottom
TPJ958 "TP_SMD" TP_1.0_SMD 2092.51,1001.98 r180 bottom
TPJ959 "TP_SMD" TP_1.0_SMD 2145.61,1086.58 r90 bottom
TPJ960 "TP_SMD" TP_1.0_SMD 2122.01,1283.38 r90 bottom
TPJ961 "TP_SMD" TP_1.0_SMD 2124.01,1183.08 r180 bottom
U1 "EFM8BB22F16G-C-QFN28" QFN28_SI_EFM8 3409.45,1377.95 r0 top
U100 "TS3A44159" UQFN16_M040_1.8X2.6_TI_RSV 1590.16,1187.99 r0 top
U600 "LP3982ILD-ADJ" WSON8_M050_3.0X2.5_EP_TI_NGM 725.68,2171.16 r0 top
U603 "TLV70536" DSBGA4_M040_0.8X0.8_TI_YFP 1746.06,1277.56 r180 top
U606 "MCP6001T" SC70-5 1059.06,1010.83 r270 top
U622 "MCP6001T" SC70-5 2657.48,1011.81 r180 top
U700 "SIP32431" TDFN4_M050_1.6X1.2_EP_VISH 964.57,1312.99 r90 top
U701 "LP3982ILD-ADJ" WSON8_M050_3.0X2.5_EP_TI_NGM 1264.76,1231.3 r270 top
U702 "TS3A4751" QFN14_M040_2.0X2.0_TI_RUC 1681.1,1443.9 r180 top
U703 "LTC6102CDD" DFN8_M050_3.0X3.0_EP_LT_DD 1135.83,1570.87 r180 top
U704 "AD8656" MSOP8_M065_W3.0 1088.58,1755.91 r0 top
U800 "74LVC4066" DHVQFN14_M050_2.5X3_EP_NXP 2791.34,1716.54 r270 top
U802 "74LVC4066" DHVQFN14_M050_2.5X3_EP_NXP 2791.34,1539.37 r270 top
U803 "74LVC1T45" X2-DFN1010-6_M035_DIODES 2770.67,1867.13 r0 top
U804 "74LVC2G125" DSBGA8_M050_0.9X1.9_TI_YZP 2030.51,1501.97 r180 top
U805 "TS3A4751" QFN14_M040_2.0X2.0_TI_RUC 2550.2,1459.45 r90 top
U806 "74LVC4066" DHVQFN14_M050_2.5X3_EP_NXP 2791.34,1362.2 r270 top
U807 "74LVC1T45" X2-DFN1010-6_M035_DIODES 2811.54,1030.51 r270 top
U808 "74LVC8T245" VQFN24_M050_3.5X5.5_EP_TI_RHL 2496.06,1694.88 r0 top
U809 "74LVC2G125" DSBGA8_M050_0.9X1.9_TI_YZP 2059.06,1640.75 r180 top
U810 "74LVC4066" DHVQFN14_M050_2.5X3_EP_NXP 2791.34,1185.04 r270 top
U812 "TS3A4751" QFN14_M040_2.0X2.0_TI_RUC 2641.73,1183.07 r90 top
U860 "74LVC1T45" X2-DFN1010-6_M035_DIODES 2045.28,1889.76 r180 top
U861 "74LVC1T45" X2-DFN1010-6_M035_DIODES 2661.42,1570.87 r90 top
U862 "74LVC1T45" X2-DFN1010-6_M035_DIODES 2458.66,1503.94 r90 top
U863 "74LVC1T45" X2-DFN1010-6_M035_DIODES 2665.35,1330.71 r90 top
U900 "EFM32GG12B410F1024GL120-A" BGA120_M050_7.0X7.0_EFM32GGR 1834.65,1751.97 r180 top
U901 "M24C02" TDFN8_M050_2.0X3.0_EP 2043.09,1966.54 r0 top
U902 "MX25R8035F" BGA8_M040_1.24X1.75_WLCSP 2102.36,1350.39 r0 top
U910 "ADC084S021" VSSOP10_M050_W3.0_TI_DGS 1906.5,1378.94 r0 top
U950 "TS3A4751" QFN14_M040_2.0X2.0_TI_RUC 2095.47,1767.72 r270 top
X900 "48 MHz" X_KDS_DSX211SH_2.0X1.65-4 1799.21,1958.66 r0 top

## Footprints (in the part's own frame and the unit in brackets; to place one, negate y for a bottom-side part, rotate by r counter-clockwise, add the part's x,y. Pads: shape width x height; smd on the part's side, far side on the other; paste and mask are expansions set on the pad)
ADHESIVE_PAD_25.0X4.0 [mil] "Adhesive for Sharp Display"
  Top Layer keep-out region: 0,157.5 0,0.02 984.25,0.02 984.25,157.5 0,157.5
  silkscreen extent 0,0 984,158, body extent 0,0 984,158, height 8
BAT_HOLD_MPD_BK-912_CR2032 [mil] "MPD Battery Holder BK-912 (for CR2032)"
  rrect20% 110x200 smd: 1(-430,0) 1(430,0)
  round 157.48 smd paste-295.67 mask-82.68: 2(0,0)
  body extent -450,-394 450,393, height 171
BGA8_M040_1.24X1.75_WLCSP [mm] "BGA, 8 pin. U100"
  round 0.21 smd mask+0.05: A1(-0.35,0.4) A3(0.35,0.4) B2(0,0.2) C1(-0.35,0) C3(0.35,0) D2(0,-0.2) E1(-0.35,-0.4) E3(0.35,-0.4)
  body extent -0.63,-0.89 0.63,0.88, height 0.52
BGA120_M050_7.0X7.0_EFM32GGR [mm] "BGA, 120 Leads, Body 7.0x7.0mmx1,30mm, Pitch 0.50mm (191111)"
  round 0.2 smd mask+0.04: A1(-3,3) A2(-2.5,3) A3(-2,3) A4(-1.5,3) A5(-1,3) A6(-0.5,3) A7(0,3) A8(0.5,3) A9(1,3) A10(1.5,3) A11(2,3) A12(2.5,3) A13(3,3) B1(-3,2.5) B2(-2.5,2.5) B3(-2,2.5) B4(-1.5,2.5) B5(-1,2.5) B6(-0.5,2.5) B7(0,2.5) B8(0.5,2.5) B9(1,2.5) B10(1.5,2.5) B11(2,2.5) B12(2.5,2.5) B13(3,2.5) C1(-3,2) C2(-2.5,2) C3(-2,2) C4(-1.5,2) C5(-1,2) C6(-0.5,2) C7(0,2) C8(0.5,2) C9(1,2) C10(1.5,2) C11(2,2) C12(2.5,2) C13(3,2) D1(-3,1.5) D2(-2.5,1.5) D3(-2,1.5) D11(2,1.5) D12(2.5,1.5) D13(3,1.5) E1(-3,1) E2(-2.5,1) E3(-2,1) E11(2,1) E12(2.5,1) E13(3,1) F1(-3,0.5) F2(-2.5,0.5) F3(-2,0.5) F11(2,0.5) F12(2.5,0.5) F13(3,0.5) G1(-3,0) G2(-2.5,0) G3(-2,0) G11(2,0) G12(2.5,0) G13(3,0) H1(-3,-0.5) H2(-2.5,-0.5) H3(-2,-0.5) H11(2,-0.5) H12(2.5,-0.5) H13(3,-0.5) J1(-3,-1) J2(-2.5,-1) J3(-2,-1) J11(2,-1) J12(2.5,-1) J13(3,-1) K1(-3,-1.5) K2(-2.5,-1.5) K3(-2,-1.5) K11(2,-1.5) K12(2.5,-1.5) K13(3,-1.5) L1(-3,-2) L2(-2.5,-2) L3(-2,-2) L4(-1.5,-2) L5(-1,-2) L6(-0.5,-2) L7(0,-2) L8(0.5,-2) L9(1,-2) L10(1.5,-2) L11(2,-2) L12(2.5,-2) L13(3,-2) M1(-3,-2.5) M2(-2.5,-2.5) M3(-2,-2.5) M4(-1.5,-2.5) M5(-1,-2.5) M6(-0.5,-2.5) M7(0,-2.5) M8(0.5,-2.5) M9(1,-2.5) M10(1.5,-2.5) M11(2,-2.5) M12(2.5,-2.5) M13(3,-2.5) N1(-3,-3) N2(-2.5,-3) N3(-2,-3) N4(-1.5,-3) N5(-1,-3) N6(-0.5,-3) N7(0,-3) N8(0.5,-3) N9(1,-3) N10(1.5,-3) N11(2,-3) N12(2.5,-3) N13(3,-3)
  body extent -3.5,-3.5 3.5,3.5, height 1.3
C0201 [mm] "Capacitor, 9291, HiDens (170502)"
  rrect25% 0.36x0.32 smd paste-0.015 mask+0.05: 1(-0.275,0) 2(0.275,0)
  Top Layer pour cut-out: -0.075,-0.2 -0.075,0.2 0.075,0.2 0.075,-0.2
  body extent -0.32,-0.13 0.32,0.13, height 0.3
C0402 [mm] "Chip Capacitor, 2-Leads, Body 1.0x0.5mm, IPC High Density (190308)"
  rrect20% 0.5x0.5 smd mask+0.051: 1(-0.5,0) 2(0.5,0)
  Top Layer pour cut-out: -0.225,-0.3 -0.225,0.3 0.225,0.3 0.225,-0.3
  body extent -0.5,-0.25 0.5,0.25, height 0.6
C0603 [mm] "Capacitor, 0603, HiDens (190130)"
  rrect25% 0.8x0.85 smd: 1(-0.7,0) 2(0.7,0)
  Top Layer pour cut-out: -0.275,-0.55 -0.275,0.55 0.275,0.55 0.275,-0.55
  body extent -0.88,-0.48 0.87,0.48, height 0.95
C0805 [mm] "Capacitor, 0805 HiDens (190717)"
  rrect25% 0.95x1.35 smd: 1(-0.8,0) 2(0.8,0)
  body extent -1.1,-0.64 1.1,0.64, height 1.45
CK_DP3T_JS203011SCQN [mm] "Switch, C & K DP3T JS203011SCQN (190314)"
  rrect50% 1.2x2.5 smd: 1(-4,-2.75) 2(-2,-2.75) 3(2,-2.75) 4(4,-2.75) 5(-4,2.75) 6(-2,2.75) 7(2,2.75) 8(4,2.75)
  body extent -6.5,-3.75 6.5,3.75, height 5.22
COIL_0402 [mm] "COIL_0402_L (3D from Wurth) (190308)"
  rrect20% 0.55x0.5 smd mask+0.051: 1(-0.525,0) 2(0.525,0)
  Top Layer pour cut-out: -0.225,-0.3 -0.225,0.3 0.225,0.3 0.225,-0.3
  body extent -0.5,-0.25 0.5,0.25, height 0.5
COIL_WURTH_CBF_0603 [mm] "COIL_WURTH_CBF_0603 (= L0603_0.8_L) (181031)"
  rrect10% 0.67x0.88 smd: 1(-0.665,0) 2(0.665,0)
  body extent -0.87,-0.48 0.87,0.48, height 0.95
DFN8_M050_3.0X3.0_EP_LT_DD [mm] "DFN 8 Lead, Pitch 0.5, 3.0x3.0x0.75 Exposed Pad, Linear Tech (171004)"
  rrect50% 0.7x0.25 smd paste-0.025 mask+0.07: 1(-1.4,0.75) 2(-1.4,0.25) 3(-1.4,-0.25) 4(-1.4,-0.75) 5(1.4,-0.75) 6(1.4,-0.25) 7(1.4,0.25) 8(1.4,0.75)
  rect 1x1.8 smd paste-1 mask+0: 9(0,0)
  Top Layer region: 0.825,1.2 -0.693,1.2 -0.825,1.095 -0.825,-1.2 0.825,-1.2
  body extent -1.56,-1.55 1.56,1.55, height 0.8
DFN2111-7_M050_1.2X2.1_NXP [mm] "DFN2111-7 NXP Pitch 035 1.2x2.1x0.5, NXP (190312)"
  rrect20% 0.53x0.19 smd mask+0.05: 1(-0.415,0.75) 2(-0.415,0.25) 3(-0.415,-0.25) 4(-0.415,-0.75) 5(0.415,-0.5) 6(0.415,0) 7(0.415,0.5)
  body extent -0.6,-1.05 0.6,1.05, height 0.51
DHVQFN14_M050_2.5X3_EP_NXP [mm] "DHVQFN, 14 Leads, 2.5x3.0x0.85, Pitch 0.50, Thermal Pad 1.0x1.5 (190314)"
  oval 0.3x0.7 smd: 1(-0.25,1.45) 7(-0.25,-1.45) 8(0.25,-1.45) 14(0.25,1.45)
  oval 0.7x0.3 smd: 2(-1.2,1) 3(-1.2,0.5) 4(-1.2,0) 5(-1.2,-0.5) 6(-1.2,-1) 9(1.2,-1) 10(1.2,-0.5) 11(1.2,0) 12(1.2,0.5) 13(1.2,1)
  rrect10% 1x1.5 smd: 17(0,0)
  body extent -1.25,-1.5 1.25,1.5, height 1.1
DSBGA4_M040_0.8X0.8_TI_YFP [mm] "DS-BGA, 4 Leads, Body 0.8x0.8 H:0.5, Pitch 0.40"
  round 0.23 smd mask+0.04: A1(-0.2,0.2) A2(0.2,0.2) B1(-0.2,-0.2) B2(0.2,-0.2)
  body extent -0.4,-0.4 0.4,0.4, height 0.51
DSBGA8_M050_0.9X1.9_TI_YZP [mm] "DS-BGA, 8 Leads, Body 0.9x1.9 H:0.5, Pitch 0.50"
  round 0.23 smd: A1(-0.25,0.75) A2(0.25,0.75) B1(-0.25,0.25) B2(0.25,0.25) C1(-0.25,-0.25) C2(0.25,-0.25) D1(-0.25,-0.75) D2(0.25,-0.75)
  body extent -0.45,-0.95 0.45,0.95, height 0.51
FCI_10137065_USB-C_RCPT [mm] "FCI AMPHENOL 10137065 USB-C Receptacle (Slot PinInPaste) (180404)"
  oval 1.3x2.6 hole 0.7 slot 2 at 90 deg: 25(-4.32,-3.05) 26(4.32,-3.05)
  oval 1.3x2.6 on Top Paste: 25(-4.32,-3.05) 26(4.32,-3.05)
  oval 1.2x2.489 on Top Paste: 27(-4.32,2)
  oval 1.2x2.5 hole 0.6 slot 1.9 at 90 deg paste+0: 27(-4.32,2)
  oval 1.638x1.194 on Top Paste: 27(-4.025,1.35)
  oval 1.647x1.2 hole 0.6 slot 1.247 at 0 deg: 27(-4.025,1.35)
  oval 1.847x1.2 hole 0.6 slot 1.247 at 0 deg: 28(4.025,1.35)
  oval 1.841x1.194 on Top Paste: 28(4.025,1.35)
  oval 1.2x2.5 hole 0.6 slot 1.9 at 90 deg: 28(4.32,2)
  oval 1.194x2.489 on Top Paste: 28(4.32,2)
  rrect20% 0.27x0.9 smd mask+0.076: A1(-2.625,2.7) A2(-2.125,2.7) A3(-1.625,2.7) A4(-1.125,2.7) A5(-0.625,2.7) A6(-0.125,2.7) A7(0.375,2.7) A8(0.875,2.7) A9(1.375,2.7) A10(1.875,2.7) A11(2.375,2.7) A12(2.875,2.7)
  rrect20% 0.27x0.8 smd mask+0.076: B1(2.625,1.1) B2(2.125,1.1) B3(1.625,1.1) B4(1.125,1.1) B5(0.625,1.1) B6(0.125,1.1) B7(-0.375,1.1) B8(-0.875,1.1) B9(-1.375,1.1) B10(-1.875,1.1) B11(-2.375,1.1) B12(-2.875,1.1)
  round 0 hole 0.6 unplated mask+0.102: M1(-3.6,0)
  round 0 hole 0.5 slot 0.85 at 0 deg unplated mask+0.102: M2(3.6,0)
  Top Layer keep-out region: -3.9,-4.85 3.9,-4.85 3.9,0.4 -3.9,0.4
  body extent -4.47,-5.3 4.47,2.85, height 3.14
HDR_M254-1X2 [mm] "Connector; Header; 2 Position (170508)"
  round 1.6 hole 1: 1(0,0) 2(2.54,0)
  body extent -1.07,-1.17 3.61,1.17, height 8.12
HDR_M254-1X3_NO_3D [mm] "No 3D model for this component"
  round 1.6 hole 1: 1(0,0) 2(2.54,0) 3(5.08,0)
HDR_M254-1X16_NO_3D [mm] "No 3D model for this component (200325)"
  round 1.5 hole 0.9: 1(0,0) 2(2.54,0) 3(5.08,0) 4(7.62,0) 5(10.16,0) 6(12.7,0) 7(15.24,0) 8(17.78,0) 9(20.32,0) 10(22.86,0) 11(25.4,0) 12(27.94,0) 13(30.48,0) 14(33.02,0) 15(35.56,0) 16(38.1,0)
HDR_SULLINS_M127_PEG-2X10 [mil] "Sullins, GRPB102VQS (180319)"
  rrect50% 30x87 smd: 1(-25,-72.5) 2(-25,72.5) 3(25,-72.5) 4(25,72.5) 5(75,-72.5) 6(75,72.5) 7(125,-72.5) 8(125,72.5) 9(175,-72.5) 10(175,72.5) 11(225,-72.5) 12(225,72.5) 13(275,-72.5) 14(275,72.5) 15(325,-72.5) 16(325,72.5) 17(375,-72.5) 18(375,72.5) 19(425,-72.5) 20(425,72.5)
  round 0 hole 39.37 unplated mask+3.94: M1(0,0) M2(400,0)
  body extent -50,-100 450,101, height 197
HOLE_3.0_5.0_PL [mm] "Hole 3.0 mm, Plated (171122)"
  round 5 hole 3: 1(0,0)
HOLE_3.0_NPL [mm] "HOLE_3.0_NPL (170815)"
  round 0 hole 3 unplated mask+0.2: 1(0,0)
  body extent -1.5,-1.5 1.5,1.5
HRS_U.FL-R-SMT [mm] "COAX_HIROSE_U.FL_CL331-0471 (170228)"
  rrect20% 1.05x1.1 smd mask+0.051: 1(0,-1.6)
  rrect20% 1.05x2.25 smd mask+0.051: 2(1.5,0) 3(-1.5,0)
  Top Layer pour cut-out: 0.85,-0.9 -0.85,-0.9 -0.85,-0.9 -0.85,1.2 0.85,1.2 0.85,1.2
  body extent -1.3,-1.3 1.3,1.55, height 0.9
KLS_KLS1-242D_FPC_0.5-10 [mm] "KLS1-242D-1.2-10 (3D IS FROM MOL 5450) (201021)"
  rrect50% 0.3x1.25 smd mask+0.076: 1(0,0) 2(0.5,0) 3(1,0) 4(1.5,0) 5(2,0) 6(2.5,0) 7(3,0) 8(3.5,0) 9(4,0) 10(4.5,0)
  rrect5% 2x2.45 smd: 11(-1.69,-2.6) 12(6.19,-2.6)
  body extent -2.85,-5.05 7.35,-0.05, height 1.2
LABEL_4CORNERS_19.0X6.0 [mil]
  silkscreen extent -374,-118 374,118
LABEL_P101_PIN_TABLE_SL [mil]
  silkscreen extent -94,-492 94,492
LED_0402 [mm] "Chip Diode, 2-Leads, Body 1.00x0.50mm, IPC High Density (170127)"
  rrect10% 0.45x0.6 smd: 1(-0.45,0) 2(0.45,0)
  body extent -0.55,-0.33 0.55,0.33, height 0.25
LED_0402_CAT2 [mm] "(200921)"
  rrect10% 0.45x0.6 smd: 1(-0.45,0) 2(0.45,0)
  body extent -0.55,-0.33 0.55,0.33, height 0.25
LED_AVAGO_HSMF-C165-4 [mm] "LED (dual) Avago HSMF-C165 Grn+Red 1.6x0.8x0.5 (200226)"
  rrect20% 0.7x0.4 smd: 1(-0.65,-0.35) 2(-0.65,0.35) 3(0.65,0.35) 4(0.65,-0.35)
  body extent -0.8,-0.4 0.8,0.4, height 0.52
LED_LUMEX_SML-LX0404-4 [mm] "LED, LUMEX, SML LX0404 1.0x1.0x0.25 NB! Pin numbering (180111)"
  rrect25% 0.45x0.45 smd mask+0.05: 1(-0.425,-0.425) 2(-0.425,0.425) 3(0.425,0.425) 4(0.425,-0.425)
  body extent -0.5,-0.5 0.5,0.5, height 0.31
LOGO_BEE_H7.0 [mil] "Silicon Labs Logo Bee (210415)"
  silkscreen extent -141,0 142,272
LOGO_SEGGER_10.0X5.0_SM [mil] "Logo, Segger 10.0x5.0, Top Solder + M19 + Top Overlay"
LOGO_SILABS_W14.0_SILK [mil] "LOGO_SILABS_W14.0 SILKSCREEN ONLY"
  silkscreen extent 1,0 551,269
LOGO_SILABS_W18.0 [mil]
  silkscreen extent 1,1 669,328
MSOP8_M065_W3.0 [mm] "MSOP, 8-Leads, Body 3.0x3.0mm, Pitch 0.65mm (170921)"
  rrect20% 0.889x0.42 smd mask+0.048: 1(-2.105,0.975) 2(-2.105,0.325) 3(-2.105,-0.325) 4(-2.105,-0.975) 5(2.106,-0.975) 6(2.106,-0.325) 7(2.106,0.325) 8(2.106,0.975)
  body extent -1.55,-1.55 1.55,1.55, height 1.11
OLED_LS013B7DH03 [mil] "LS013B7DH03 (200526)"
  body extent -524,-732 524,521, height 150
QFN14_M040_2.0X2.0_TI_RUC [mm] "QFN 14 Leads, Pitch 0.4 mm, 2.0 x 2.0 H: 0.37, TI: RUC (180613)"
  rrect20% 0.68x0.2 smd: 1(-0.885,0.8) 2(-0.885,0.4) 3(-0.885,0) 4(-0.885,-0.4) 5(-0.885,-0.8) 8(0.885,-0.8) 9(0.885,-0.4) 10(0.885,0) 11(0.885,0.4) 12(0.885,0.8)
  rrect20% 0.2x0.68 smd: 6(-0.2,-0.885) 7(0.2,-0.885) 13(0.2,0.885) 14(-0.2,0.885)
  body extent -1,-1 1,1, height 0.41
QFN28_SI_EFM8 [mm] "QFN, 28-Leads, Body 5.00x5.00mm, Pitch 0.50mm, Thermal Pad 3.25x3.25mm, IPC High Density"
  rect 0.95x0.3 smd mask+0.05: 1(-2.4,1.5) 2(-2.4,1) 3(-2.4,0.5) 4(-2.4,0) 5(-2.4,-0.5) 6(-2.4,-1) 7(-2.4,-1.5) 15(2.4,-1.5) 16(2.4,-1) 17(2.4,-0.5) 18(2.4,0) 19(2.4,0.5) 20(2.4,1) 21(2.4,1.5)
  rect 0.3x0.95 smd mask+0.05: 8(-1.5,-2.4) 9(-1,-2.4) 10(-0.5,-2.4) 11(0,-2.4) 12(0.5,-2.4) 13(1,-2.4) 14(1.5,-2.4)
  rect 0.35x0.95 smd mask+0.05: 22(1.5,2.4) 23(1,2.4) 24(0.5,2.4) 25(0,2.4) 26(-0.5,2.4) 27(-1,2.4) 28(-1.5,2.4)
  rect 3.35x3.35 smd mask+0.05: 29(0,0)
  body extent -2.5,-2.5 2.5,2.5, height 0.8
R0201 [mm] "Resistor (Chip2PinSM127P600-8N) (170921)"
  rrect25% 0.34x0.32 smd: 1(-0.3,0) 2(0.3,0)
  Top Layer pour cut-out: -0.1,-0.2 -0.1,0.2 0.1,0.2 0.1,-0.2
  body extent -0.32,-0.13 0.32,0.13, height 0.3
R0402 [mm] "Chip Resistor, 2-Leads, Body 1.0x0.5mm, HiDens (190308)"
  rrect20% 0.6x0.6 smd mask+0.051: 1(-0.45,0) 2(0.45,0)
  Top Layer pour cut-out: -0.125,-0.3 -0.125,0.3 0.125,0.3 0.125,-0.3
  body extent -0.5,-0.25 0.5,0.25, height 0.6
R0603 [mm] "Chip Resistor, 0603, HiDens (190130)"
  rrect25% 0.85x0.9 smd: 1(-0.7,0) 2(0.7,0)
  Top Layer pour cut-out: -0.25,-0.575 -0.25,0.575 0.25,0.575 0.25,-0.575
  body extent -0.88,-0.48 0.87,0.48, height 0.95
R1206 [mm] "Resistor, 1206, HiDens (191114)"
  rrect25% 0.85x1.65 smd paste-0.04 mask+0.07: 1(-1.425,0) 2(1.425,0)
  body extent -1.6,-0.8 1.6,0.8, height 1
RES_MNR04-8 [mm] "Resistor Array, ROHM MNR04 8-Pin 2.0x1.0x0.35 (!80615)"
  rrect20% 0.4x0.5 smd: 1(-0.75,-0.45) 4(0.75,-0.45) 5(0.75,0.45) 8(-0.75,0.45)
  rrect20% 0.3x0.5 smd: 2(-0.25,-0.45) 3(0.25,-0.45) 6(0.25,0.45) 7(-0.25,0.45)
  body extent -1,-0.4 1,0.4, height 0.5
SC70-5 [mm] "SC70-5 = SOT353, HiDens (170511)"
  rrect25% 0.6x0.4 smd paste-0.03 mask+0.05: 1(-0.95,0.65) 2(-0.95,0) 3(-0.95,-0.65) 4(0.95,-0.65) 5(0.95,0.65)
  body extent -1.12,-0.97 1.16,1.03, height 0.95
SOT563 [mm] "SOT563 (_M050_W1.2_), 6-Leads, Body 1.60x1.20, Pitch 0.5, HiDens (170926)"
  rrect25% 0.6x0.3 smd: 1(-0.65,0.5) 2(-0.65,0) 3(-0.65,-0.5) 4(0.65,-0.5) 5(0.65,0) 6(0.65,0.5)
  body extent -0.65,-0.85 0.65,0.85, height 0.6
SOT563_DIODES [mm] "SOT563 (_M050_W1.2_), 6-Leads, Body 1.60x1.20, Pitch 0.5, HiDens (170926)"
  rrect25% 0.5x0.375 smd: 1(-0.85,0.5) 2(-0.85,0) 3(-0.85,-0.5) 4(0.85,-0.5) 5(0.85,0) 6(0.85,0.5)
  body extent -0.66,-0.85 0.65,0.85, height 0.6
SW_ALPS_SKRHAAE010 [mm] "Switch, ALPS / ALPINE (200615)"
  rrect20% 1.35x1 smd: 1(-3.575,1.425) 2(-3.575,0) 3(-3.575,-1.425) 4(3.575,1.425) 5(3.575,0) 6(3.575,-1.425)
  rrect20% 2x1.8 smd: 7(0,4.05) 8(0,-4.05)
  round 0 hole 0.75 mask+0.102: M1(0,1.9)
  round 0 hole 1.05 mask+0.102: M2(0,-1.9)
  body extent -3.74,-3.75 3.74,3.75, height 5
SW_CK_PTS810_SJM_250 [mm] "Switch C&K PTS810_SJM_250 (grey button) (180319)"
  rrect20% 1.05x0.65 smd: 1(-2.075,1.075) 2(2.075,1.075) 3(-2.075,-1.075) 4(2.075,-1.075)
  body extent -2.29,-1.6 2.29,1.6, height 2.5
TAB_V-CUT_L7.0_W2.4 [mil] "TAB V_CUT, Length 7.0, Width 2.4"
TDFN4_M050_1.6X1.2_EP_VISH [mm] "TDFN, 4-Leads, Body 1.60x1.20mm, IPC HiDens (180111)"
  rrect10% 0.55x0.3 smd: 1(-0.725,0.25) 2(-0.725,-0.25) 3(0.725,-0.25) 4(0.725,0.25)
  rrect10% 0.5x0.86 smd paste-0.05: 5(0,0)
  body extent -0.8,-0.6 0.8,0.6, height 0.61
TDFN8_M050_2.0X3.0_EP [mm] "TDFN8_M050_2.0x3.0_EP (170921)"
  rrect20% 0.75x0.3 smd: 1(-1.45,0.75) 2(-1.45,0.25) 3(-1.45,-0.25) 4(-1.45,-0.75) 5(1.45,-0.75) 6(1.45,-0.25) 7(1.45,0.25) 8(1.45,0.75)
  rrect10% 1.5x1.4 smd: 9(0,0)
  body extent -1.5,-1 1.5,1, height 1.01
TP_1.0_SMD [mm] "Test Point, 1.0 mm, SMD (170509)"
  round 1 smd paste-0.501: 1(0,0)
  body extent -0.5,-0.5 0.5,0.5, height 0.04
UQFN16_M040_1.8X2.6_TI_RSV [mm] "UQFN 16 Leads, Pitch 0.4, 1.9x2.6x0.5, TI: RSV (190816)"
  rrect20% 0.7x0.2 smd paste+0 mask+0.05: 1(-0.75,0.6)
  rrect20% 0.6x0.2 smd paste+0 mask+0.05: 2(-0.8,0.2) 3(-0.8,-0.2) 4(-0.8,-0.6) 9(0.8,-0.6) 10(0.8,-0.2) 11(0.8,0.2) 12(0.8,0.6)
  rrect20% 0.2x0.6 smd paste+0 mask+0.05: 5(-0.6,-1.2) 6(-0.2,-1.2) 7(0.2,-1.2) 8(0.6,-1.2) 13(0.6,1.2) 14(0.2,1.2) 15(-0.2,1.2) 16(-0.6,1.2)
  body extent -0.9,-1.3 0.9,1.3, height 0.56
VQFN24_M050_3.5X5.5_EP_TI_RHL [mm] "VQFN 24 Leads, Pitch 0.50 3.5x5.0x0.9, TI: RHL (171011)"
  rrect20% 0.28x0.99 smd: 1(-0.75,2.795) 12(-0.75,-2.795) 13(0.75,-2.795) 24(0.75,2.795)
  rrect20% 0.99x0.28 smd: 2(-1.795,2.25) 3(-1.795,1.75) 4(-1.795,1.25) 5(-1.795,0.75) 6(-1.795,0.25) 7(-1.795,-0.25) 8(-1.795,-0.75) 9(-1.795,-1.25) 10(-1.795,-1.75) 11(-1.795,-2.25) 14(1.795,-2.25) 15(1.795,-1.75) 16(1.795,-1.25) 17(1.795,-0.75) 18(1.795,-0.25) 19(1.795,0.25) 20(1.795,0.75) 21(1.795,1.25) 22(1.795,1.75) 23(1.795,2.25)
  rrect5% 2.05x4.05 smd: 25(0,0)
  Top Layer region: 0.39,-3.26 0.39,-2 -0.39,-2 -0.39,-3.26 -0.39,-3.266 -0.385,-3.277 -0.377,-3.285 -0.366,-3.29 -0.36,-3.29 -0.36,-3.29 -0.14,-3.29 -0.134,-3.29 -0.123,-3.285 -0.115,-3.277 -0.11,-3.266 -0.11,-3.26 -0.11,-3.26 -0.11,-2.32 -0.11,-2.316 -0.107,-2.309 -0.101,-2.303 -0.094,-2.3 -0.09,-2.3 -0.09,-2.3 0.09,-2.3 0.094,-2.3 0.101,-2.303 0.107,-2.309 0.11,-2.316 0.11,-2.32 0.11,-2.32 0.11,-3.26 0.11,-3.266 0.115,-3.277 0.123,-3.285 0.134,-3.29 0.14,-3.29 0.14,-3.29 0.36,-3.29 0.366,-3.29 0.377,-3.285 0.385,-3.277 0.39,-3.266 0.39,-3.26
  Top Layer region: -0.39,3.26 -0.39,2 0.39,2 0.39,3.26 0.39,3.266 0.385,3.277 0.377,3.285 0.366,3.29 0.36,3.29 0.36,3.29 0.14,3.29 0.134,3.29 0.123,3.285 0.115,3.277 0.11,3.266 0.11,3.26 0.11,3.26 0.11,2.32 0.11,2.316 0.107,2.309 0.101,2.303 0.094,2.3 0.09,2.3 0.09,2.3 -0.09,2.3 -0.094,2.3 -0.101,2.303 -0.107,2.309 -0.11,2.316 -0.11,2.32 -0.11,2.32 -0.11,3.26 -0.11,3.266 -0.115,3.277 -0.123,3.285 -0.134,3.29 -0.14,3.29 -0.14,3.29 -0.36,3.29 -0.366,3.29 -0.377,3.285 -0.385,3.277 -0.39,3.266 -0.39,3.26
  body extent -1.75,-2.75 1.75,2.75, height 1
VSSOP10_M050_W3.0_TI_DGS [mm] "VSSOP, 10-Leads, 3.0x3.0x(max1.1), Pitch 0.50mm, (TI: DGS) (190816)"
  rrect20% 1.45x0.3 smd: 1(-2.2,1) 2(-2.2,0.5) 3(-2.2,0) 4(-2.2,-0.5) 5(-2.2,-1) 6(2.2,-1) 7(2.2,-0.5) 8(2.2,0) 9(2.2,0.5) 10(2.2,1)
  body extent -1.5,-1.5 1.5,1.5, height 1.1
WCON_1125B-1210_HOR_PEG-2X10 [mm] "WCON 2x10 header (201021)"
  rrect50% 1.27x3.175 smd: 1(-1.27,4.24) 2(-1.27,8.43) 3(1.27,4.24) 4(1.27,8.43) 5(3.81,4.24) 6(3.81,8.43) 7(6.35,4.24) 8(6.35,8.43) 9(8.89,4.24) 10(8.89,8.43) 11(11.43,4.24) 12(11.43,8.43) 13(13.97,4.24) 14(13.97,8.43) 15(16.51,4.24) 16(16.51,8.43) 17(19.05,4.24) 18(19.05,8.43) 19(21.59,4.24) 20(21.59,8.43)
  round 0 hole 1.9 unplated paste+0.91 mask+0.1: M1(0,0) M2(20.32,0)
  body extent -2.54,-7.11 22.86,9.15, height 6.1
WCON_3132_HDR_M127_SMD-2X10 [mm] "WCON_3132_HDR_M127_SMD-2X10 (210215)"
  rrect50% 0.74x2.4 smd: 1(-5.715,-1.95) 2(-5.715,1.95) 3(-4.445,-1.95) 4(-4.445,1.95) 5(-3.175,-1.95) 6(-3.175,1.95) 7(-1.905,-1.95) 8(-1.905,1.95) 9(-0.635,-1.95) 10(-0.635,1.95) 11(0.635,-1.95) 12(0.635,1.95) 13(1.905,-1.95) 14(1.905,1.95) 15(3.175,-1.95) 16(3.175,1.95) 17(4.445,-1.95) 18(4.445,1.95) 19(5.715,-1.95) 20(5.715,1.95)
  body extent -6.35,-4.53 6.35,2.84, height 6.58
WSON8_M050_3.0X2.5_EP_TI_NGM [mm] "WSON8, Pitch 0.5, 3.0x2.5x0.8 EP TI: NGM (181205)"
  rrect20% 0.5x0.25 smd mask+0.051: 1(-1.15,0.75) 2(-1.15,0.25) 3(-1.15,-0.25) 4(-1.15,-0.75) 5(1.15,-0.75) 6(1.15,-0.25) 7(1.15,0.25) 8(1.15,0.75)
  rrect10% 1.2x1.5 smd mask+0.051: 9(0,0)
  body extent -1.5,-1.25 1.5,1.25, height 0.8
X2-DFN1006-2 [mm] "Diodes case X2-DFN1006-2 part DESD5V0S1BLD (201012)"
  rrect20% 0.4x0.7 smd mask+0.04: 1(-0.35,0) 2(0.35,0)
  body extent -0.5,-0.3 0.5,0.3, height 0.41
X2-DFN1010-6_M035_DIODES [mm] "X2-DFN1010-6 Pitch 0.35 1.0x1.0x0.4, Diodes Inc (181025)"
  rrect20% 0.55x0.2 smd mask+0.04: 1(-0.35,0.35) 2(-0.35,0) 3(-0.35,-0.35) 4(0.35,-0.35) 5(0.35,0) 6(0.35,0.35)
  body extent -0.5,-0.5 0.5,0.5, height 0.41
X2-DFN2015-3_DIODES [mm] "X2-DFN2015-3 DIODES (181204)"
  rrect10% 0.5x0.31 smd mask+0.07: 1(-0.9,0.5) 2(-0.9,-0.5)
  rrect10% 0.75x0.31 smd mask+0.07: 3(0.775,0)
  Top Layer region: 0.5,0.55 0.5,-0.55 0.5,-0.57 0.485,-0.607 0.457,-0.635 0.42,-0.65 0.4,-0.65 0.4,-0.65 -0.4,-0.65 -0.42,-0.65 -0.457,-0.635 -0.485,-0.607 -0.5,-0.57 -0.5,-0.55 -0.5,-0.55 -0.5,0.55 -0.5,0.57 -0.485,0.607 -0.457,0.635 -0.42,0.65 -0.4,0.65 -0.4,0.65 0.4,0.65 0.42,0.65 0.457,0.635 0.485,0.607 0.5,0.57 0.5,0.55
  body extent -1.04,-0.79 1.04,0.79, height 0.4
X_KDS_DSX211SH_2.0X1.65-4 [mm] "X_KDS_DSX211SH_2.0X1.65-4 (190312)"
  rrect20% 0.9x0.8 smd: 1(-0.7,-0.55) 2(0.7,-0.55) 3(0.7,0.55) 4(-0.7,0.55)
  body extent -1.07,-0.87 1.07,0.87, height 0.5

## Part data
LED900: library part Yellow
LED901: library part Blue

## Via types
v1: diameter 20, hole 9.84, Top Layer to Bottom Layer, tented both sides, 1068 vias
